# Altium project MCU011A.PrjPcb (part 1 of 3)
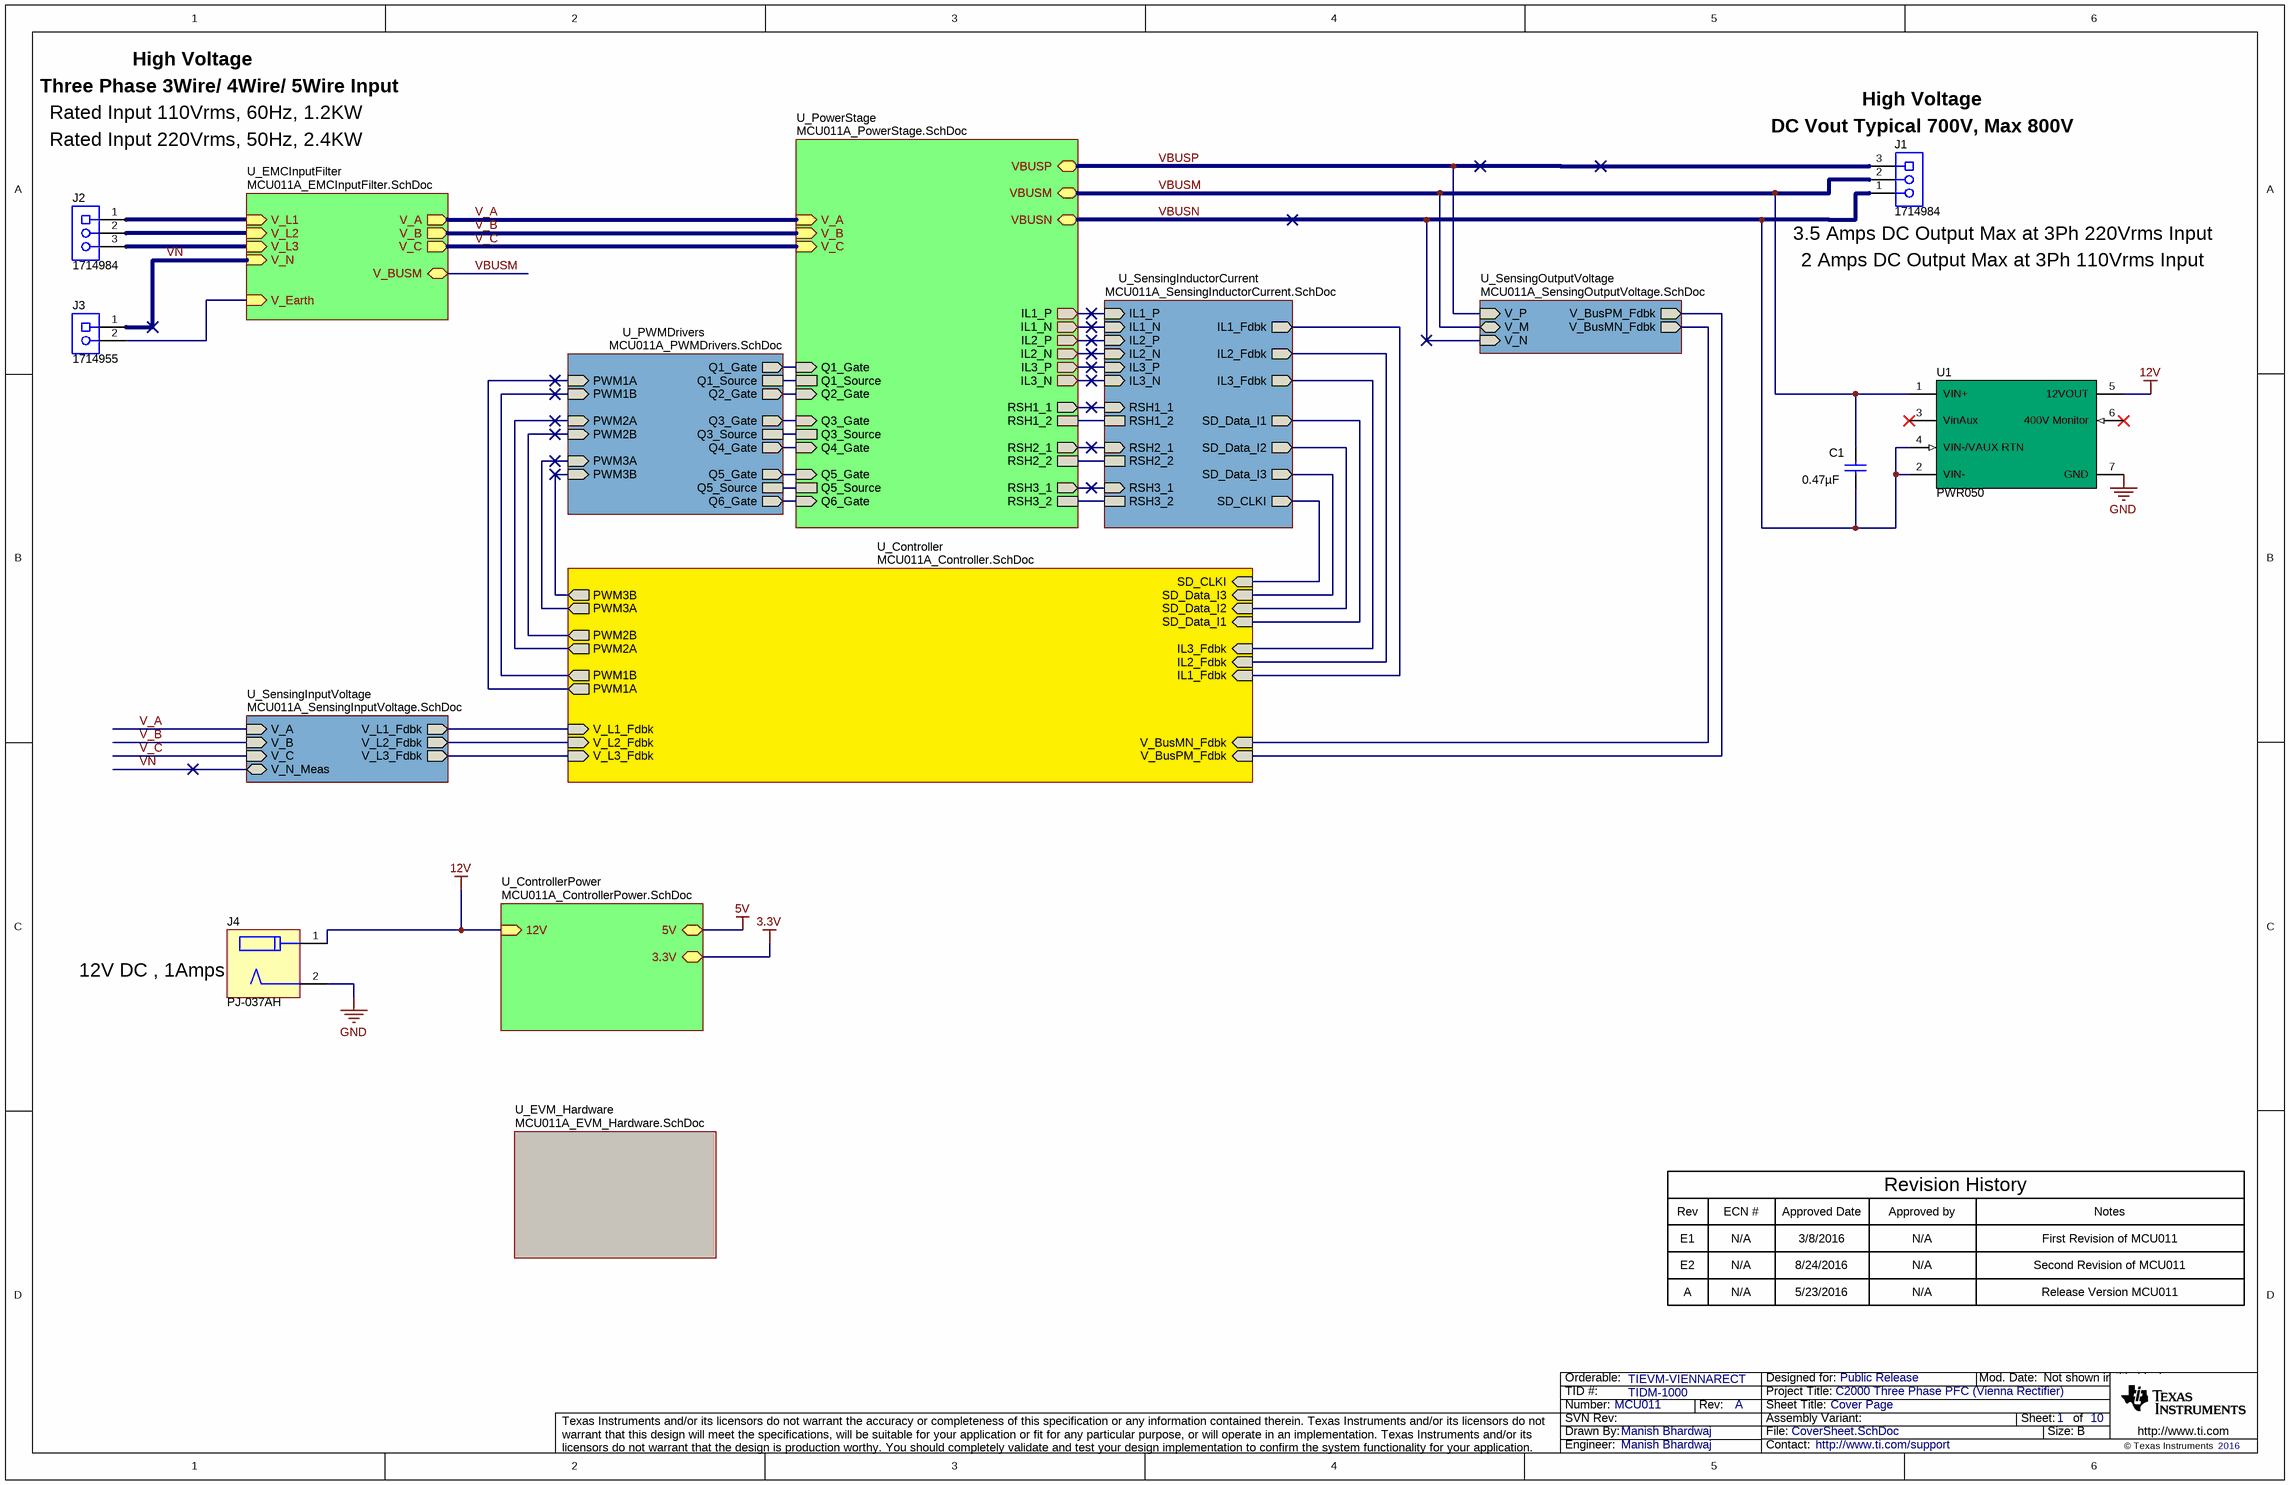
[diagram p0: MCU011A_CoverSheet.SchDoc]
CopyrightYear: 2016; EVM_orderable: TIEVM-VIENNARECT; PCB_Layout: TBD; PCB_Rev: A; PRJ_Customer: Public Release; PRJ_Engineer: Manish Bhardwaj; PRJ_Number: MCU011; PRJ_Title: C2000 Three Phase PFC (Vienna Rectifier); SCH_Rev: A; TechSupport: http://www.ti.com/support; TID: TIDM-1000
10 sheets, 500 parts. Net scope: hierarchical (ports join the sheet entries above them; power ports are global).
Board file: MCU011A_EVMBoard.PcbDoc
Sheets:
  MCU011A_CoverSheet.SchDoc
    U_PowerStage = MCU011A_PowerStage.SchDoc
    U_PWMDrivers = MCU011A_PWMDrivers.SchDoc
    U_ControllerPower = MCU011A_ControllerPower.SchDoc
    U_EVM_Hardware = MCU011A_EVM_Hardware.SchDoc
    U_EMCInputFilter = MCU011A_EMCInputFilter.SchDoc
    U_SensingInductorCurrent = MCU011A_SensingInductorCurrent.SchDoc
    U_SensingInputVoltage = MCU011A_SensingInputVoltage.SchDoc
    U_SensingOutputVoltage = MCU011A_SensingOutputVoltage.SchDoc
    U_Controller = MCU011A_Controller.SchDoc

## Sheet MCU011A_CoverSheet.SchDoc: Cover Page
size 431 x 279 mm; Date: Not shown in title block; ApprovedBy: Not shown in title block; CheckedBy: Not shown in title block; Author: Not shown in title block; CompanyName: Not shown in title block; DrawnBy: Manish Bhardwaj; Engineer: Not shown in title block; Organization: Not shown in title block; Address1: Not shown in title block; Address2: Not shown in title block; Address3: Not shown in title block; Address4: Not shown in title block; DocumentNumber: 1; Revision: Use project parameter SCH_Rev; SheetNumber: 1; SheetTotal: 10; PageSetup: Record=PageOptions¦CenterHorizontal=True¦CenterVertical=True¦PrintScale=1.00¦XCorrection=1.00¦YCorrection=1.00¦PrintKind=0¦BorderSize=5000000¦LeftOffset=0¦BottomOffset=0¦Orientation=2¦PaperLength=1000¦PaperWidth=1000¦Scale=100¦PaperSource=15¦PrintQuality=-3¦MediaType=1¦DitherType=10¦PrintScaleMode=1¦PaperKind=Letter (8.5 x 11")¦PaperIndex=1

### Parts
C1  ValueDisplayed: 0.47µF  [1812_254]  (hidden comment: 1812Y5000474KXTWS2)
J1  1714984  [Phoenix_1714984]
J2  1714984  [Phoenix_1714984]
J3  1714955  [Phoenix_1714955]
J4  PJ-037AH  [CUI_PJ-037AH]
U1  PWR050  [PWR050]

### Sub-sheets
U_Controller = MCU011A_Controller.SchDoc: PWM3A (out), PWM1A (out), PWM3B (out), SD_Data_I1 (in), SD_CLKI (in), SD_Data_I2 (in), SD_Data_I3 (in), V_L1_Fdbk (in), V_L2_Fdbk (in), V_L3_Fdbk (in), PWM1B (out), PWM2A (out), PWM2B (out), IL1_Fdbk (in), IL2_Fdbk (in), IL3_Fdbk (in), V_BusMN_Fdbk (in), V_BusPM_Fdbk (in)
U_ControllerPower = MCU011A_ControllerPower.SchDoc: 12V (in), 5V, 3.3V
U_EMCInputFilter = MCU011A_EMCInputFilter.SchDoc: V_N (in), V_L2 (in), V_L3 (in), V_L1 (in), V_Earth (in), V_C (out), V_B (out), V_A (out), V_BUSM
U_EVM_Hardware = MCU011A_EVM_Hardware.SchDoc: no entries
U_PowerStage = MCU011A_PowerStage.SchDoc: Q1_Gate (in), Q2_Gate (in), Q1_Source, Q3_Gate (in), Q4_Gate (in), Q3_Source, Q5_Gate (in), Q6_Gate (in), Q5_Source, RSH1_1 (out), RSH1_2, RSH2_1 (out), RSH2_2, RSH3_1 (out), RSH3_2, IL1_P (out), IL3_P (out), IL2_P (out), IL1_N (out), IL3_N (out), IL2_N (out), V_A (in), V_B (in), V_C (in), VBUSP, VBUSM, VBUSN
U_PWMDrivers = MCU011A_PWMDrivers.SchDoc: PWM1A (in), PWM1B (in), Q1_Gate (out), Q1_Source, PWM2A (in), PWM2B (in), Q3_Gate (out), Q4_Gate (out), Q3_Source, PWM3A (in), PWM3B (in), Q5_Gate (out), Q6_Gate (out), Q5_Source, Q2_Gate (out)
U_SensingInductorCurrent = MCU011A_SensingInductorCurrent.SchDoc: IL1_N (in), IL1_P (in), IL1_Fdbk (out), IL2_N (in), IL2_P (in), IL2_Fdbk (out), IL3_N (in), IL3_P (in), IL3_Fdbk (out), RSH1_1 (in), RSH1_2, SD_Data_I1 (out), SD_CLKI (out), RSH2_1 (in), RSH2_2, SD_Data_I2 (out), RSH3_1 (in), RSH3_2, SD_Data_I3 (out)
U_SensingInputVoltage = MCU011A_SensingInputVoltage.SchDoc: V_L1_Fdbk (out), V_A (in), V_L2_Fdbk (out), V_B (in), V_L3_Fdbk (out), V_C (in), V_N_Meas
U_SensingOutputVoltage = MCU011A_SensingOutputVoltage.SchDoc: V_BusPM_Fdbk (out), V_P (in), V_BusMN_Fdbk (out), V_N (in), V_M

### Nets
12V: J4.1 U1.5(12VOUT) ; sheet U_ControllerPower/12V
GND: J4.2 U1.7(GND)
IL1_Fdbk: sheet U_SensingInductorCurrent/IL1_Fdbk, sheet U_Controller/IL1_Fdbk
IL1_N: sheet U_PowerStage/IL1_N, sheet U_SensingInductorCurrent/IL1_N
IL1_P: sheet U_PowerStage/IL1_P, sheet U_SensingInductorCurrent/IL1_P
IL2_Fdbk: sheet U_SensingInductorCurrent/IL2_Fdbk, sheet U_Controller/IL2_Fdbk
IL2_N: sheet U_PowerStage/IL2_N, sheet U_SensingInductorCurrent/IL2_N
IL2_P: sheet U_PowerStage/IL2_P, sheet U_SensingInductorCurrent/IL2_P
IL3_Fdbk: sheet U_SensingInductorCurrent/IL3_Fdbk, sheet U_Controller/IL3_Fdbk
IL3_N: sheet U_PowerStage/IL3_N, sheet U_SensingInductorCurrent/IL3_N
IL3_P: sheet U_PowerStage/IL3_P, sheet U_SensingInductorCurrent/IL3_P
PWM1A: sheet U_PWMDrivers/PWM1A, sheet U_Controller/PWM1A
PWM1B: sheet U_PWMDrivers/PWM1B, sheet U_Controller/PWM1B
PWM2A: sheet U_PWMDrivers/PWM2A, sheet U_Controller/PWM2A
PWM2B: sheet U_PWMDrivers/PWM2B, sheet U_Controller/PWM2B
PWM3A: sheet U_PWMDrivers/PWM3A, sheet U_Controller/PWM3A
PWM3B: sheet U_PWMDrivers/PWM3B, sheet U_Controller/PWM3B
Q1_Gate: sheet U_PowerStage/Q1_Gate, sheet U_PWMDrivers/Q1_Gate
Q1_Source: sheet U_PowerStage/Q1_Source, sheet U_PWMDrivers/Q1_Source
Q2_Gate: sheet U_PowerStage/Q2_Gate, sheet U_PWMDrivers/Q2_Gate
Q3_Gate: sheet U_PowerStage/Q3_Gate, sheet U_PWMDrivers/Q3_Gate
Q3_Source: sheet U_PowerStage/Q3_Source, sheet U_PWMDrivers/Q3_Source
Q4_Gate: sheet U_PowerStage/Q4_Gate, sheet U_PWMDrivers/Q4_Gate
Q5_Gate: sheet U_PowerStage/Q5_Gate, sheet U_PWMDrivers/Q5_Gate
Q5_Source: sheet U_PowerStage/Q5_Source, sheet U_PWMDrivers/Q5_Source
Q6_Gate: sheet U_PowerStage/Q6_Gate, sheet U_PWMDrivers/Q6_Gate
RSH1_1: sheet U_PowerStage/RSH1_1, sheet U_SensingInductorCurrent/RSH1_1
RSH1_2: sheet U_PowerStage/RSH1_2, sheet U_SensingInductorCurrent/RSH1_2
RSH2_1: sheet U_PowerStage/RSH2_1, sheet U_SensingInductorCurrent/RSH2_1
RSH2_2: sheet U_PowerStage/RSH2_2, sheet U_SensingInductorCurrent/RSH2_2
RSH3_1: sheet U_PowerStage/RSH3_1, sheet U_SensingInductorCurrent/RSH3_1
RSH3_2: sheet U_PowerStage/RSH3_2, sheet U_SensingInductorCurrent/RSH3_2
SD_CLKI: sheet U_SensingInductorCurrent/SD_CLKI, sheet U_Controller/SD_CLKI
SD_Data_I1: sheet U_SensingInductorCurrent/SD_Data_I1, sheet U_Controller/SD_Data_I1
SD_Data_I2: sheet U_SensingInductorCurrent/SD_Data_I2, sheet U_Controller/SD_Data_I2
SD_Data_I3: sheet U_SensingInductorCurrent/SD_Data_I3, sheet U_Controller/SD_Data_I3
V_A: sheet U_PowerStage/V_A, sheet U_EMCInputFilter/V_A, sheet U_SensingInputVoltage/V_A
V_B: sheet U_PowerStage/V_B, sheet U_EMCInputFilter/V_B, sheet U_SensingInputVoltage/V_B
V_BusMN_Fdbk: sheet U_SensingOutputVoltage/V_BusMN_Fdbk, sheet U_Controller/V_BusMN_Fdbk
V_BusPM_Fdbk: sheet U_SensingOutputVoltage/V_BusPM_Fdbk, sheet U_Controller/V_BusPM_Fdbk
V_C: sheet U_PowerStage/V_C, sheet U_EMCInputFilter/V_C, sheet U_SensingInputVoltage/V_C
V_Earth: J3.2 ; sheet U_EMCInputFilter/V_Earth
V_L1: J2.1 ; sheet U_EMCInputFilter/V_L1
V_L1_Fdbk: sheet U_SensingInputVoltage/V_L1_Fdbk, sheet U_Controller/V_L1_Fdbk
V_L2: J2.2 ; sheet U_EMCInputFilter/V_L2
V_L2_Fdbk: sheet U_SensingInputVoltage/V_L2_Fdbk, sheet U_Controller/V_L2_Fdbk
V_L3: J2.3 ; sheet U_EMCInputFilter/V_L3
V_L3_Fdbk: sheet U_SensingInputVoltage/V_L3_Fdbk, sheet U_Controller/V_L3_Fdbk
VBUSM: C1.1 J1.2 U1.1(VIN+) ; sheet U_PowerStage/VBUSM, sheet U_EMCInputFilter/V_BUSM, sheet U_SensingOutputVoltage/V_M  [project net V_M]
VBUSN: C1.2 J1.1 U1.2(VIN-) U1.4(VIN-/VAUX_RTN) ; sheet U_PowerStage/VBUSN, sheet U_SensingOutputVoltage/V_N
VBUSP: J1.3 ; sheet U_PowerStage/VBUSP, sheet U_SensingOutputVoltage/V_P
VN: J3.1 ; sheet U_EMCInputFilter/V_N, sheet U_SensingInputVoltage/V_N_Meas  [project net V_N_Meas]

Not connected (* = marked no-connect by the designer): U1 3(VinAux)* 6(400V_Monitor)*

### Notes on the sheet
- High Voltage
- Three Phase 3Wire/ 4Wire/ 5Wire Input
- Rated Input 110Vrms, 60Hz, 1.2KW
- Rated Input 220Vrms, 50Hz, 2.4KW
- (near J1) DC Vout Typical 700V, Max 800V
- (near J1) 3.5 Amps DC Output Max at 3Ph 220Vrms Input
- 2 Amps DC Output Max at 3Ph 110Vrms Input
- 12V DC , 1Amps
- Rev
- E1
- ECN #
- N/A
- Approved Date
- 3/8/2016
- Approved by
- Revision History
- Notes
- First Revision of MCU011
- E2
- A
- 8/24/2016
- 5/23/2016
- Second Revision of MCU011
- Release Version MCU011

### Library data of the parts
C1 = 1812Y5000474KXTWS2: CAP, CERM, 0.47 µF, 500 V, +/- 10%, X7R, 1812; Manufacturer: Knowles Capacitors; Polarized: N; CompType: Capacitor; Value: 0.47uF; U/M: EA; Cap_F: 0.00000047; Tolerance_%: 10; Value1: Unknown; VDC_V: 500; Value2: 500V; TaMin_C: -55; TaMax_C: 125; Cap_Case: 1812; SizeArea_mm2: 14.4; SizeAreaWB_mm2: 23.1; SizeX_mm: 4.5; SizeY_mm: 3.2; SizeZ_mm: 2.54; AEC Category: Q200
J1 J2 = 1714984: Terminal Block, 3x1, 9.52MM, TH; Manufacturer: Phoenix Contact; SymbolCreator: a0412235
J3 = 1714955: Terminal Block, 2x1, 6.35mm, Green, TH; Manufacturer: Phoenix Contact; SymbolCreator: a0412235; Pitch_mm: 6.35; Gender: Female; Shrouded: Y; Row_Count: 1
J4 = PJ-037AH: Power Jack, 2mm, R/A, TH; Manufacturer: CUI Inc.; SymbolCreator: Altium; Pitch_mm: 6; Gender: Male; Shrouded: N; Row_Count: 1
U1 = PWR050: PCBA, UCC28600EVM-400V-12V; Manufacturer: Texas Instruments; SymbolCreator: a0412235

## Sheet MCU011A_PowerStage.SchDoc: Vienna Rectifier Power Stage
size 558 x 431 mm; Date: Not shown in title block; ApprovedBy: Not shown in title block; CheckedBy: Not shown in title block; Author: Not shown in title block; CompanyName: Not shown in title block; DrawnBy: Manish Bhardwaj; Engineer: Not shown in title block; Organization: Not shown in title block; Address1: Not shown in title block; Address2: Not shown in title block; Address3: Not shown in title block; Address4: Not shown in title block; DocumentNumber: 1; Revision: Use project parameter SCH_Rev; SheetNumber: 3; SheetTotal: 10; PageSetup: Record=PageOptions¦CenterHorizontal=True¦CenterVertical=True¦PrintScale=1.00¦XCorrection=1.00¦YCorrection=1.00¦PrintKind=0¦BorderSize=5000000¦LeftOffset=0¦BottomOffset=0¦Orientation=2¦PaperLength=1000¦PaperWidth=1000¦Scale=100¦PaperSource=15¦PrintQuality=600¦MediaType=1¦DitherType=10¦PaperKind=Letter¦PrintScaleMode=1
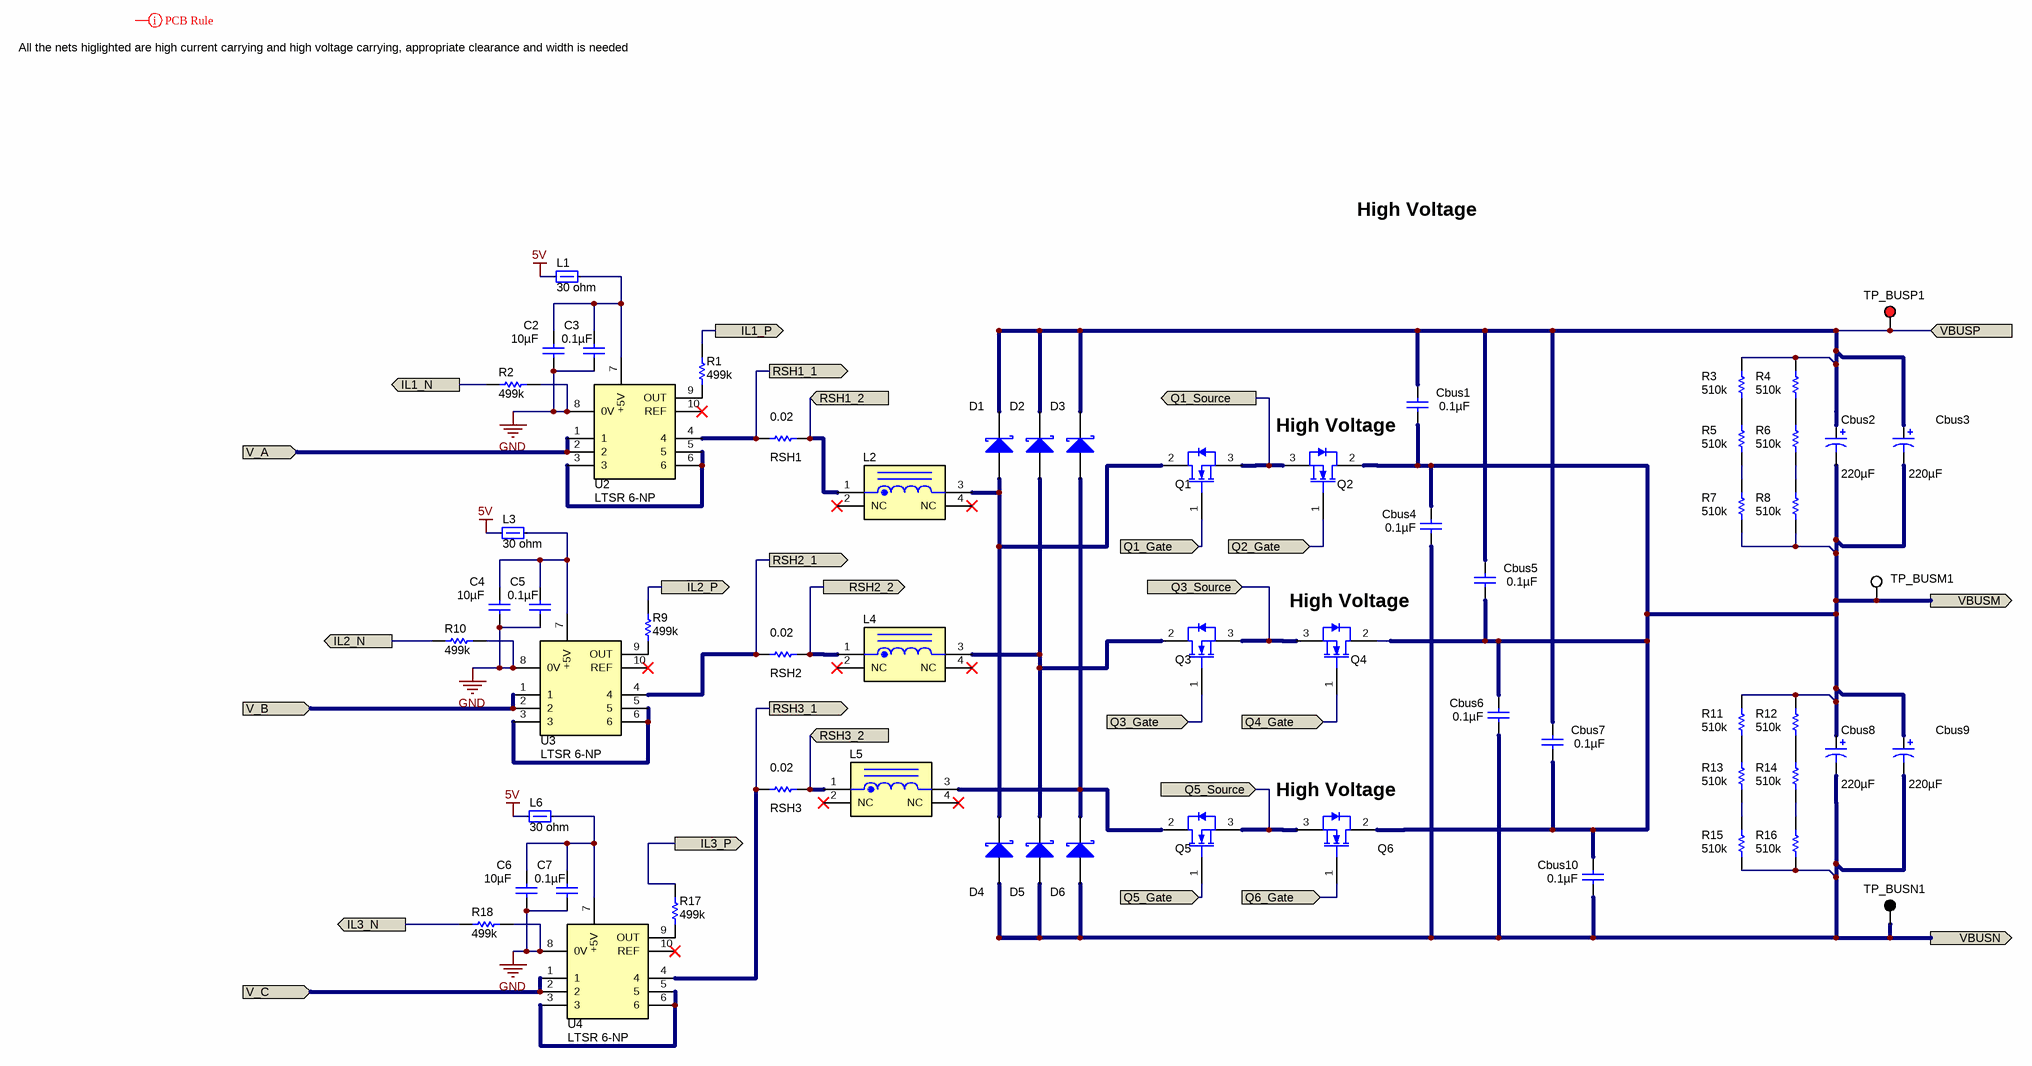
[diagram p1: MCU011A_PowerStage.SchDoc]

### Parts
C2  ValueDisplayed: 10µF  [1206_190]  (hidden comment: C1206C106K3RACTU)
C3  ValueDisplayed: 0.1µF  [0805_HV]  (hidden comment: C0805C104K3RACTU)
C4  ValueDisplayed: 10µF  [1206_190]  (hidden comment: C1206C106K3RACTU)
C5  ValueDisplayed: 0.1µF  [0805_HV]  (hidden comment: C0805C104K3RACTU)
C6  ValueDisplayed: 10µF  [1206_190]  (hidden comment: C1206C106K3RACTU)
C7  ValueDisplayed: 0.1µF  [0805_HV]  (hidden comment: C0805C104K3RACTU)
Cbus1  ValueDisplayed: 0.1µF  [CAPRR1500W80L1800T770H1210]  (hidden comment: ECW-F6104JL)
Cbus2  ValueDisplayed: 220µF  [B43504_3500x3000]  (hidden comment: B43504C5227M)
Cbus3  ValueDisplayed: 220µF  [B43504_3500x3000]  (hidden comment: B43504C5227M)
Cbus4  ValueDisplayed: 0.1µF  [CAPRR1500W80L1800T770H1210]  (hidden comment: ECW-F6104JL)
Cbus5  ValueDisplayed: 0.1µF  [CAPRR1500W80L1800T770H1210]  (hidden comment: ECW-F6104JL)
Cbus6  ValueDisplayed: 0.1µF  [CAPRR1500W80L1800T770H1210]  (hidden comment: ECW-F6104JL)
Cbus7  ValueDisplayed: 0.1µF  [CAPRR1500W80L1800T770H1210]  (hidden comment: ECW-F6104JL)
Cbus8  ValueDisplayed: 220µF  [B43504_3500x3000]  (hidden comment: B43504C5227M)
Cbus9  ValueDisplayed: 220µF  [B43504_3500x3000]  (hidden comment: B43504C5227M)
Cbus10  ValueDisplayed: 0.1µF  [CAPRR1500W80L1800T770H1210]  (hidden comment: ECW-F6104JL)
D1  C4D08120A  [TO-220-2_HORIZ_INV]  (value not drawn)
D2  C4D08120A  [TO-220-2_HORIZ_INV]  (value not drawn)
D3  C4D08120A  [TO-220-2_HORIZ_INV]  (value not drawn)
D4  C4D08120A  [TO-220-2_HORIZ_INV]  (value not drawn)
D5  C4D08120A  [TO-220-2_HORIZ_INV]  (value not drawn)
D6  C4D08120A  [TO-220-2_HORIZ_INV]  (value not drawn)
L1  value 30 ohm  [0805_HV]  (hidden comment: MPZ2012S300AT000)
L2  53PR116-292  [53PR116]  (value not drawn)
L3  value 30 ohm  [0805_HV]  (hidden comment: MPZ2012S300AT000)
L4  53PR116-292  [53PR116]  (value not drawn)
L5  53PR116-292  [53PR116]  (value not drawn)
L6  value 30 ohm  [0805_HV]  (hidden comment: MPZ2012S300AT000)
Q1  IPP65R190C7FKSA1  [TO-220AB_HORIZONTAL]  (value not drawn)
Q2  IPP65R190C7FKSA1  [TO-220AB_HORIZONTAL]  (value not drawn)
Q3  IPP65R190C7FKSA1  [TO-220AB_HORIZONTAL]  (value not drawn)
Q4  IPP65R190C7FKSA1  [TO-220AB_HORIZONTAL]  (value not drawn)
Q5  IPP65R190C7FKSA1  [TO-220AB_HORIZONTAL]  (value not drawn)
Q6  IPP65R190C7FKSA1  [TO-220AB_HORIZONTAL]  (value not drawn)
R1  ValueDisplayed: 499k  [0603]  (hidden comment: ERJ-3EKF4993V)
R2  ValueDisplayed: 499k  [0603]  (hidden comment: ERJ-3EKF4993V)
R3  ValueDisplayed: 510k  [2010]  (hidden comment: CRCW2010510KJNEF)
R4  ValueDisplayed: 510k  [2010]  (hidden comment: CRCW2010510KJNEF)
R5  ValueDisplayed: 510k  [2010]  (hidden comment: CRCW2010510KJNEF)
R6  ValueDisplayed: 510k  [2010]  (hidden comment: CRCW2010510KJNEF)
R7  ValueDisplayed: 510k  [2010]  (hidden comment: CRCW2010510KJNEF)
R8  ValueDisplayed: 510k  [2010]  (hidden comment: CRCW2010510KJNEF)
R9  ValueDisplayed: 499k  [0603]  (hidden comment: ERJ-3EKF4993V)
R10  ValueDisplayed: 499k  [0805]  (hidden comment: CRCW0805499KFKEA)
R11  ValueDisplayed: 510k  [2010]  (hidden comment: CRCW2010510KJNEF)
R12  ValueDisplayed: 510k  [2010]  (hidden comment: CRCW2010510KJNEF)
R13  ValueDisplayed: 510k  [2010]  (hidden comment: CRCW2010510KJNEF)
R14  ValueDisplayed: 510k  [2010]  (hidden comment: CRCW2010510KJNEF)
R15  ValueDisplayed: 510k  [2010]  (hidden comment: CRCW2010510KJNEF)
R16  ValueDisplayed: 510k  [2010]  (hidden comment: CRCW2010510KJNEF)
R17  ValueDisplayed: 499k  [0603]  (hidden comment: ERJ-3EKF4993V)
R18  ValueDisplayed: 499k  [0603]  (hidden comment: ERJ-3EKF4993V)
RSH1  ValueDisplayed: 0.02  [2512]  (hidden comment: CRA2512-FZ-R020ELF)
RSH2  ValueDisplayed: 0.02  [2512]  (hidden comment: CRA2512-FZ-R020ELF)
RSH3  ValueDisplayed: 0.02  [2512]  (hidden comment: CRA2512-FZ-R020ELF)
TP_BUSM1  5012  [Keystone5012]  (value not drawn)
TP_BUSN1  5011  [Keystone5011]  (value not drawn)
TP_BUSP1  5010  [Keystone5010]  (value not drawn)
U2  LTSR 6-NP  [LTSR6-NP]
U3  LTSR 6-NP  [LTSR6-NP]
U4  LTSR 6-NP  [LTSR6-NP]

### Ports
IL1_N (out), IL1_P (out), IL2_N (out), IL2_P (out), IL3_N (out), IL3_P (out), Q1_Gate (in), Q1_Source, Q2_Gate (in), Q3_Gate (in), Q3_Source, Q4_Gate (in), Q5_Gate (in), Q5_Source, Q6_Gate (in), RSH1_1 (out), RSH1_2, RSH2_1 (out), RSH2_2, RSH3_1 (out), RSH3_2, V_A (in), V_B (in), V_C (in), VBUSM, VBUSN, VBUSP

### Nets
5V: L1.2 L3.2 L6.2
GND: C2.2 C3.2 C4.2 C5.2 C6.2 C7.2 R2.2 R10.2 R18.2 U2.8(0V) U3.8(0V) U4.8(0V)
IL1_N: R2.1 ; port IL1_N
IL1_P: R1.2 ; port IL1_P
IL2_N: R10.1 ; port IL2_N
IL2_P: R9.2 ; port IL2_P
IL3_N: R18.1 ; port IL3_N
IL3_P: R17.2 ; port IL3_P
Q1_Gate: Q1.1(G) ; port Q1_Gate
Q1_Source: Q1.3(S) Q2.3(S) ; port Q1_Source
Q2_Gate: Q2.1(G) ; port Q2_Gate
Q3_Gate: Q3.1(G) ; port Q3_Gate
Q3_Source: Q3.3(S) Q4.3(S) ; port Q3_Source
Q4_Gate: Q4.1(G) ; port Q4_Gate
Q5_Gate: Q5.1(G) ; port Q5_Gate
Q5_Source: Q5.3(S) Q6.3(S) ; port Q5_Source
Q6_Gate: Q6.1(G) ; port Q6_Gate
RSH1_1: RSH1.1 U2.4 ; port RSH1_1
RSH1_2: L2.1 RSH1.2 ; port RSH1_2
RSH2_1: RSH2.1 U3.4 ; port RSH2_1
RSH2_2: L4.1 RSH2.2 ; port RSH2_2
RSH3_1: RSH3.1 U4.4 ; port RSH3_1
RSH3_2: L5.1 RSH3.2 ; port RSH3_2
V_A: U2.1 U2.2 ; port V_A
V_B: U3.1 U3.2 ; port V_B
V_C: U4.1 U4.2 ; port V_C
V_M: Cbus1.2 Cbus2.2(-) Cbus3.2(-) Cbus4.1 Cbus5.2 Cbus6.1 Cbus7.2 Cbus8.1(+) Cbus9.1(+) Cbus10.1 Q2.2(D) Q4.2(D) Q6.2(D) R7.1 R8.1 R11.2 R12.2 TP_BUSM1.1 ; port VBUSM
VBUSN: Cbus4.2 Cbus6.2 Cbus8.2(-) Cbus9.2(-) Cbus10.2 D4.2(A) D5.2(A) D6.2(A) R15.1 R16.1 TP_BUSN1.1 ; port VBUSN
VBUSP: Cbus1.1 Cbus2.1(+) Cbus3.1(+) Cbus5.1 Cbus7.1 D1.1(K) D2.1(K) D3.1(K) R3.2 R4.2 TP_BUSP1.1 ; port VBUSP
NetC2_1: C2.1 C3.1 L1.1 U2.7(+5V)
NetC4_1: C4.1 C5.1 L3.1 U3.7(+5V)
NetC6_1: C6.1 C7.1 L6.1 U4.7(+5V)
NetD1_2: D1.2(A) D4.1(K) L2.3 Q1.2(D)
NetD2_2: D2.2(A) D5.1(K) L4.3 Q3.2(D)
NetD3_2: D3.2(A) D6.1(K) L5.3 Q5.2(D)
NetR1_1: R1.1 U2.9(OUT)
NetR3_1: R3.1 R5.2
NetR4_1: R4.1 R6.2
NetR5_1: R5.1 R7.2
NetR6_1: R6.1 R8.2
NetR9_1: R9.1 U3.9(OUT)
NetR11_1: R11.1 R13.2
NetR12_1: R12.1 R14.2
NetR13_1: R13.1 R15.2
NetR14_1: R14.1 R16.2
NetR17_1: R17.1 U4.9(OUT)
NetU2_3: U2.3 U2.5 U2.6
NetU3_3: U3.3 U3.5 U3.6
NetU4_3: U4.3 U4.5 U4.6

Not connected (* = marked no-connect by the designer): L2 2(NC)* 4(NC)*; L4 2(NC)* 4(NC)*; L5 2(NC)* 4(NC)*; U2 10(REF)*; U3 10(REF)*; U4 10(REF)*

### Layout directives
rule Undefined: (no net found under the mark)

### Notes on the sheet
- All the nets higlighted are high current carrying and high voltage carrying, appropriate clearance and width is needed
- High Voltage
- (near Q4) High Voltage
- (near Q6) High Voltage

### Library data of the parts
C2 C4 C6 = C1206C106K3RACTU: CAP, CERM, 10 µF, 25 V, +/- 10%, X7R, 1206_190; Manufacturer: Kemet; Polarized: N; CompType: Capacitor; Value: 10uF; U/M: EA; Cap_F: 0.00001; Tolerance_%: 10; Value1: Unknown; VDC_V: 25; Value2: 25V; TaMin_C: -55; TaMax_C: 125; Cap_Case: 1206; AEC Category: Q200
C3 C5 C7 = C0805C104K3RACTU: CAP, CERM, 0.1 µF, 25 V, +/- 10%, X7R, 0805; Manufacturer: Kemet; Polarized: N; CompType: Capacitor; Value: 0.1uF; U/M: EA; Cap_F: 0.0000001; Tolerance_%: 10; ESR_ohm: 0.064; Value1: 0.064 ohm; VDC_V: 25; Value2: 25V; IRMS_A: 1.64; TaMin_C: -55; TaMax_C: 125; Cap_Case: 0805; AEC Category: Q200
Cbus1 Cbus4-Cbus7 Cbus10 = ECW-F6104JL: CAP, Film, 0.1 µF, 630 V, +/- 5%, TH; Manufacturer: Panasonic; Polarized: N; CompType: Capacitor; Value: 0.1uF; U/M: EA; Cap_F: 0.0000001; Tolerance_%: 5; Value1: Unknown; VDC_V: 630; Value2: 630V; TaMin_C: -40; TaMax_C: 105; Cap_Case: Radial 18x7.7x13.6; AEC Category: Q200
Cbus2 Cbus3 Cbus8 Cbus9 = B43504C5227M: CAP, AL, 220 µF, 450 V, +/- 20%, 0.73 ohm, TH; Manufacturer: TDK; Polarized: Y; CompType: Capacitor; Value: 220uF; U/M: EA; Cap_F: 0.00022; Tolerance_%: 20; VDC_V: 450; Value2: 450V; ESR_ohm: 0.73; IRMS_A: 1.2; TaMin_C: -40; TaMax_C: 105; Cap_Case: 35x30mm; AEC Category: Q200; AEC Qualified: N
D1-D6 = C4D08120A: Diode, Schottky, 1200 V, 8 A, TH; Manufacturer: Cree; U/M: EA; Vf_V: 1.8; Value: 1200V; Value1: 8A; Value2: 1.8V; Io_A: 8; Vr_V: 1200; TJmax_C: 175; RJC_CperW: 1.26; AEC Category: Q101; AEC Qualified: N
L1 L3 L6 = MPZ2012S300AT000: Ferrite Bead, 30 ohm @ 100 MHz, 6 A, 0805; Manufacturer: TDK; Imax_A: 6; DCR_ohm: 0.01; Value1: 0.01 ohm; Value2: 6A; ZTyp@100MHz_Ohm: 30
L2 L4 L5 = 53PR116-292: Inductor, 0.2 ohm, TH; Manufacturer: Vitec Corporation; SymbolCreator: a0411947; DCR_ohm: 0.2; Value1: 0.2 ohm; Value2: A; SizeAreaWB_mm2: 2452.56; SizeArea_mm2: 2258.06; SizeX_mm: 44.45; SizeY_mm: 50.8; SizeZ_mm: 53.34; AEC Category: Q200; AEC Qualified: N
Q1-Q6 = IPP65R190C7: MOSFET, N-CH, 700 V, 13 A, TO-220AB; Manufacturer: Infineon Technologies; Alternate Manufacturer: None; U/M: EA; ChType: N; Value: 700V; VdsMax_V: 700; Value1: ? ohm; Value2: 23 nC; QgTyp_nC: 23; Vgs_V: 20; IdsMax_A: 13; AEC Category: Q101
R1 R2 R9 R17 R18 = ERJ-3EKF4993V: RES, 499 k, 1%, 0.1 W, AEC-Q200 Grade 0, 0603; Manufacturer: Panasonic; CompType: Resistor; Value: 499k; Res_ohm: 499000; Tolerance_%: 1; Power_W: 0.1; Value2: 0.1W; VDC_V: 75; TempCo: 100 ppm/C; SizeArea_mm2: 1.28; SizeX_mm: 1.6; SizeY_mm: 0.8; EIA_Code: E96; U/M: EA; AEC Category: Q200; AEC Qualified: Y; AEC Grade: 0
R3-R8 R11-R16 = CRCW2010510KJNEF: RES, 510 k, 5%, 0.75 W, AEC-Q200 Grade 0, 2010; Manufacturer: Vishay-Dale; CompType: Resistor; Value: 510k; Res_ohm: 510000; Tolerance_%: 5; Power_W: 0.75; Value2: 0.75W; VDC_V: 400; TempCo: 200 ppm/C; SizeArea_mm2: 12.5; SizeY_mm: 2.5; SizeZ_mm: 1.66; EIA_Code: E24; U/M: EA; AEC Category: Q200; AEC Qualified: Y; AEC Grade: 0
R10 = CRCW0805499KFKEA: RES, 499 k, 1%, 0.125 W, 0805; Manufacturer: Vishay-Dale; CompType: Resistor; Value: 499k; Res_ohm: 499000; Tolerance_%: 1; Power_W: 0.125; Value2: 0.125W; VDC_V: 150; TempCo: 100 ppm/C; EIA_Code: E96; U/M: EA; AEC Category: Q200
RSH1-RSH3 = CRA2512-FZ-R020ELF: RES, 0.02, 1%, 3 W, 2512; Manufacturer: Bourns; CompType: Resistor; Value: 0.02; Value_Code: R020; Tolerance_%: 1; Power_W: 3; Value2: 3W; TempCo: 75 ppm/C; EIA_Code: E96; U/M: EA; AEC Category: Q200
TP_BUSM1 = 5012: Test Point, Multipurpose, White, TH; Manufacturer: Keystone; CompType: Test Point Loop; ContactFinish: Silver
TP_BUSN1 = 5011: Test Point, Multipurpose, Black, TH; Manufacturer: Keystone; CompType: Test Point Loop; ContactFinish: Silver
TP_BUSP1 = 5010: Test Point, Multipurpose, Red, TH; Manufacturer: Keystone; CompType: Test Point Loop; ContactFinish: Silver
U2-U4 = LTSR 6-NP: Current Transducer, AC/DC, 6A, TH; Manufacturer: LEM; SymbolCreator: Altium

## Sheet MCU011A_PWMDrivers.SchDoc: PWM Gate Drivers
size 431 x 279 mm; Date: Not shown in title block; ApprovedBy: Not shown in title block; CheckedBy: Not shown in title block; Author: Not shown in title block; CompanyName: Not shown in title block; DrawnBy: Manish Bhardwaj; Engineer: Not shown in title block; Organization: Not shown in title block; Address1: Not shown in title block; Address2: Not shown in title block; Address3: Not shown in title block; Address4: Not shown in title block; DocumentNumber: 1; Revision: Use project parameter SCH_Rev; SheetNumber: 4; SheetTotal: 10; PageSetup: Record=PageOptions¦CenterHorizontal=True¦CenterVertical=True¦PrintScale=1.00¦XCorrection=1.00¦YCorrection=1.00¦PrintKind=0¦BorderSize=5000000¦LeftOffset=0¦BottomOffset=0¦Orientation=2¦PaperLength=1000¦PaperWidth=1000¦Scale=100¦PaperSource=15¦PrintQuality=600¦MediaType=1¦DitherType=10¦PaperKind=Letter¦PrintScaleMode=1
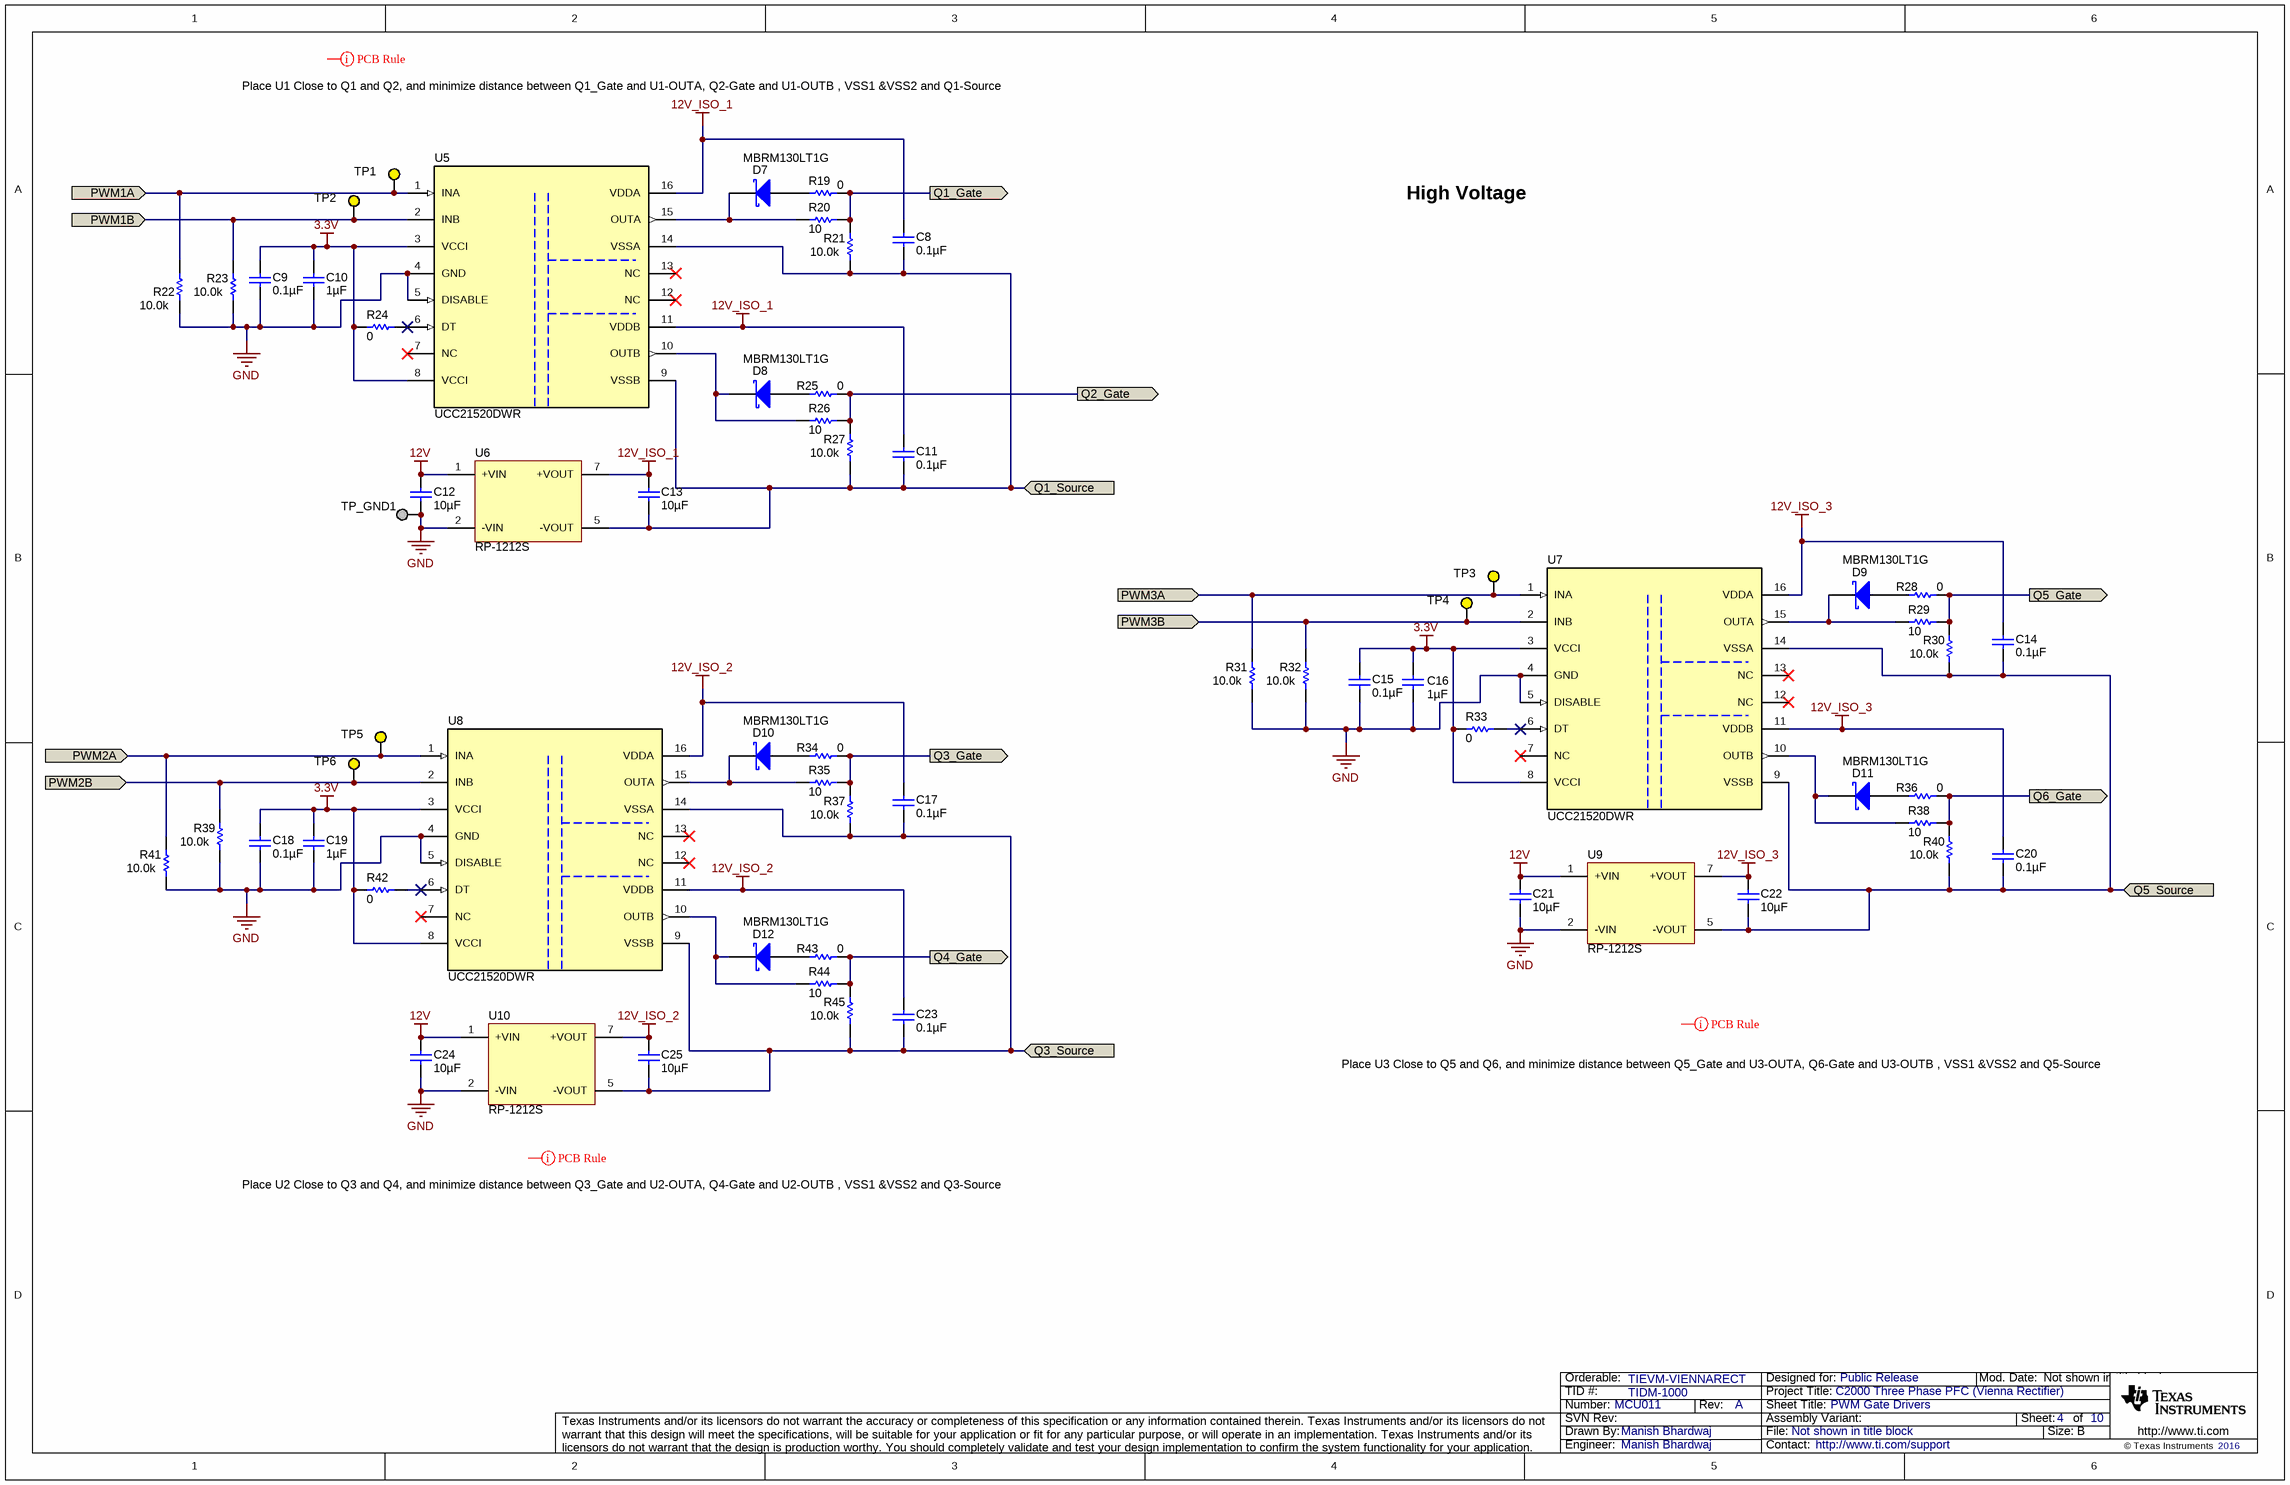
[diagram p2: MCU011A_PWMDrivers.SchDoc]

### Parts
C8  ValueDisplayed: 0.1µF  [0805_HV]  (hidden comment: C0805C104K3RACTU)
C9  ValueDisplayed: 0.1µF  [0805_HV]  (hidden comment: C0805C104K3RACTU)
C10  ValueDisplayed: 1µF  [0805_HV]  (hidden comment: GRM21BR71H105KA12L)
C11  ValueDisplayed: 0.1µF  [0805_HV]  (hidden comment: C0805C104K3RACTU)
C12  ValueDisplayed: 10µF  [1206_190]  (hidden comment: C1206C106K3RACTU)
C13  ValueDisplayed: 10µF  [1206_190]  (hidden comment: C1206C106K3RACTU)
C14  ValueDisplayed: 0.1µF  [0805_HV]  (hidden comment: C0805C104K3RACTU)
C15  ValueDisplayed: 0.1µF  [0805_HV]  (hidden comment: C0805C104K3RACTU)
C16  ValueDisplayed: 1µF  [0805_HV]  (hidden comment: GRM21BR71H105KA12L)
C17  ValueDisplayed: 0.1µF  [0805_HV]  (hidden comment: C0805C104K3RACTU)
C18  ValueDisplayed: 0.1µF  [0805_HV]  (hidden comment: C0805C104K3RACTU)
C19  ValueDisplayed: 1µF  [0805_HV]  (hidden comment: GRM21BR71H105KA12L)
C20  ValueDisplayed: 0.1µF  [0805_HV]  (hidden comment: C0805C104K3RACTU)
C21  ValueDisplayed: 10µF  [1206_190]  (hidden comment: C1206C106K3RACTU)
C22  ValueDisplayed: 10µF  [1206_190]  (hidden comment: C1206C106K3RACTU)
C23  ValueDisplayed: 0.1µF  [0805_HV]  (hidden comment: C0805C104K3RACTU)
C24  ValueDisplayed: 10µF  [1206_190]  (hidden comment: C1206C106K3RACTU)
C25  ValueDisplayed: 10µF  [1206_190]  (hidden comment: C1206C106K3RACTU)
D7  MBRM130LT1G  [POWERMITE]
D8  MBRM130LT1G  [POWERMITE]
D9  MBRM130LT1G  [POWERMITE]
D10  MBRM130LT1G  [POWERMITE]
D11  MBRM130LT1G  [POWERMITE]
D12  MBRM130LT1G  [POWERMITE]
R19  ValueDisplayed: 0  [0805_HV]  (hidden comment: CRCW08050000Z0EA)
R20  ValueDisplayed: 10  [0805_HV]  (hidden comment: CRCW080510R0JNEA)
R21  ValueDisplayed: 10.0k  [0805_HV]  (hidden comment: RT0805BRD0710KL)
R22  ValueDisplayed: 10.0k  [0805]  (hidden comment: RT0805BRD0710KL)
R23  ValueDisplayed: 10.0k  [0805]  (hidden comment: RT0805BRD0710KL)
R24  ValueDisplayed: 0  [0805]  (hidden comment: CRCW08050000Z0EA)
R25  ValueDisplayed: 0  [0805_HV]  (hidden comment: CRCW08050000Z0EA)
R26  ValueDisplayed: 10  [0805_HV]  (hidden comment: CRCW080510R0JNEA)
R27  ValueDisplayed: 10.0k  [0805_HV]  (hidden comment: RT0805BRD0710KL)
R28  ValueDisplayed: 0  [0805_HV]  (hidden comment: CRCW08050000Z0EA)
R29  ValueDisplayed: 10  [0805_HV]  (hidden comment: CRCW080510R0JNEA)
R30  ValueDisplayed: 10.0k  [0805_HV]  (hidden comment: RT0805BRD0710KL)
R31  ValueDisplayed: 10.0k  [0805]  (hidden comment: RT0805BRD0710KL)
R32  ValueDisplayed: 10.0k  [0805]  (hidden comment: RT0805BRD0710KL)
R33  ValueDisplayed: 0  [0805]  (hidden comment: CRCW08050000Z0EA)
R34  ValueDisplayed: 0  [0805_HV]  (hidden comment: CRCW08050000Z0EA)
R35  ValueDisplayed: 10  [0805_HV]  (hidden comment: CRCW080510R0JNEA)
R36  ValueDisplayed: 0  [0805_HV]  (hidden comment: CRCW08050000Z0EA)
R37  ValueDisplayed: 10.0k  [0805_HV]  (hidden comment: RT0805BRD0710KL)
R38  ValueDisplayed: 10  [0805_HV]  (hidden comment: CRCW080510R0JNEA)
R39  ValueDisplayed: 10.0k  [0805]  (hidden comment: RT0805BRD0710KL)
R40  ValueDisplayed: 10.0k  [0805_HV]  (hidden comment: RT0805BRD0710KL)
R41  ValueDisplayed: 10.0k  [0805]  (hidden comment: RT0805BRD0710KL)
R42  ValueDisplayed: 0  [0805]  (hidden comment: CRCW08050000Z0EA)
R43  ValueDisplayed: 0  [0805_HV]  (hidden comment: CRCW08050000Z0EA)
R44  ValueDisplayed: 10  [0805_HV]  (hidden comment: CRCW080510R0JNEA)
R45  ValueDisplayed: 10.0k  [0805_HV]  (hidden comment: RT0805BRD0710KL)
TP1  5014  [Keystone5014]  (value not drawn)
TP2  5014  [Keystone5014]  (value not drawn)
TP3  5014  [Keystone5014]  (value not drawn)
TP4  5014  [Keystone5014]  (value not drawn)
TP5  5014  [Keystone5014]  (value not drawn)
TP6  5014  [Keystone5014]  (value not drawn)
TP_GND1  5128  [Keystone5128]  (value not drawn)
U5  UCC21520DWR  [DW0016B_N]
U6  RP-1212S  [RP-1205S]
U7  UCC21520DWR  [DW0016B_N]
U8  UCC21520DWR  [DW0016B_N]
U9  RP-1212S  [RP-1205S]
U10  RP-1212S  [RP-1205S]

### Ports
PWM1A (in), PWM1B (in), PWM2A (in), PWM2B (in), PWM3A (in), PWM3B (in), Q1_Gate (out), Q1_Source, Q2_Gate (out), Q3_Gate (out), Q3_Source, Q4_Gate (out), Q5_Gate (out), Q5_Source, Q6_Gate (out)

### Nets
3.3V: C9.1 C10.1 C15.1 C16.1 C18.1 C19.1 R24.2 R33.2 R42.2 U5.3(VCCI) U5.8(VCCI) U7.3(VCCI) U7.8(VCCI) U8.3(VCCI) U8.8(VCCI)
12V: C12.1 C21.1 C24.1 U6.1(+VIN) U9.1(+VIN) U10.1(+VIN)
12V_ISO_1: C8.1 C11.1 C13.1 U5.11(VDDB) U5.16(VDDA) U6.7(+VOUT)
12V_ISO_2: C17.1 C23.1 C25.1 U8.11(VDDB) U8.16(VDDA) U10.7(+VOUT)
12V_ISO_3: C14.1 C20.1 C22.1 U7.11(VDDB) U7.16(VDDA) U9.7(+VOUT)
GND: C9.2 C10.2 C12.2 C15.2 C16.2 C18.2 C19.2 C21.2 C24.2 R22.1 R23.1 R31.1 R32.1 R39.1 R41.1 TP_GND1.1 U5.4(GND) U5.5(DISABLE) U6.2(-VIN) U7.4(GND) U7.5(DISABLE) U8.4(GND) U8.5(DISABLE) U9.2(-VIN) U10.2(-VIN)
PWM1A: R22.2 TP1.1 U5.1(INA) ; port PWM1A
PWM1B: R23.2 TP2.1 U5.2(INB) ; port PWM1B
PWM2A: R41.2 TP5.1 U8.1(INA) ; port PWM2A
PWM2B: R39.2 TP6.1 U8.2(INB) ; port PWM2B
PWM3A: R31.2 TP3.1 U7.1(INA) ; port PWM3A
PWM3B: R32.2 TP4.1 U7.2(INB) ; port PWM3B
Q1_Gate: R19.1 R20.2 R21.2 ; port Q1_Gate
Q1_Source: C8.2 C11.2 C13.2 R21.1 R27.1 U5.9(VSSB) U5.14(VSSA) U6.5(-VOUT) ; port Q1_Source
Q2_Gate: R25.1 R26.2 R27.2 ; port Q2_Gate
Q3_Gate: R34.1 R35.2 R37.2 ; port Q3_Gate
Q3_Source: C17.2 C23.2 C25.2 R37.1 R45.1 U8.9(VSSB) U8.14(VSSA) U10.5(-VOUT) ; port Q3_Source
Q4_Gate: R43.1 R44.2 R45.2 ; port Q4_Gate
Q5_Gate: R28.1 R29.2 R30.2 ; port Q5_Gate
Q5_Source: C14.2 C20.2 C22.2 R30.1 R40.1 U7.9(VSSB) U7.14(VSSA) U9.5(-VOUT) ; port Q5_Source
Q6_Gate: R36.1 R38.2 R40.2 ; port Q6_Gate
NetD7_1: D7.1(K) R20.1 U5.15(OUTA)
NetD7_2: D7.2(A) R19.2
NetD8_1: D8.1(K) R26.1 U5.10(OUTB)
NetD8_2: D8.2(A) R25.2
NetD9_1: D9.1(K) R29.1 U7.15(OUTA)
NetD9_2: D9.2(A) R28.2
NetD10_1: D10.1(K) R35.1 U8.15(OUTA)
NetD10_2: D10.2(A) R34.2
NetD11_1: D11.1(K) R38.1 U7.10(OUTB)
NetD11_2: D11.2(A) R36.2
NetD12_1: D12.1(K) R44.1 U8.10(OUTB)
NetD12_2: D12.2(A) R43.2
NetR24_1: R24.1 U5.6(DT)
NetR33_1: R33.1 U7.6(DT)
NetR42_1: R42.1 U8.6(DT)

Not connected (* = marked no-connect by the designer): U5 7(NC)* 12(NC)* 13(NC)*; U7 7(NC)* 12(NC)* 13(NC)*; U8 7(NC)* 12(NC)* 13(NC)*

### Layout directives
rule Undefined: (no net found under the mark)

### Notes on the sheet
- Place U1 Close to Q1 and Q2, and minimize distance between Q1_Gate and U1-OUTA, Q2-Gate and U1-OUTB , VSS1 &VSS2 and Q1-Source
- High Voltage
- Place U3 Close to Q5 and Q6, and minimize distance between Q5_Gate and U3-OUTA, Q6-Gate and U3-OUTB , VSS1 &VSS2 and Q5-Source
- Place U2 Close to Q3 and Q4, and minimize distance between Q3_Gate and U2-OUTA, Q4-Gate and U2-OUTB , VSS1 &VSS2 and Q3-Source

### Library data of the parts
C8 C9 C11 C14 C15 C17 C18 C20 C23 = C0805C104K3RACTU: as C3 on sheet MCU011A_PowerStage
C10 C16 C19 = GRM21BR71H105KA12L: CAP, CERM, 1 µF, 50 V, +/- 10%, X7R, 0805; Manufacturer: MuRata; Polarized: N; CompType: Capacitor; Value: 1uF; U/M: EA; Cap_F: 0.000001; Tolerance_%: 10; Value1: Unknown; VDC_V: 50; Value2: 50V; TaMin_C: -55; TaMax_C: 125; Cap_Case: 0805; AEC Category: Q200
C12 C13 C21 C22 C24 C25 = C1206C106K3RACTU: as C2 on sheet MCU011A_PowerStage
D7-D12 = MBRM130LT1G: Diode, Schottky, 30 V, 1 A, POWERMITE; Manufacturer: ON Semiconductor; U/M: EA; Vf_V: 0.38; Value: 30V; Value1: 1A; Value2: 0.38V; Io_A: 1; Vr_V: 30; TJmax_C: 125; AEC Category: Q101
R19 R24 R25 R28 R33 R34 R36 R42 R43 = CRCW08050000Z0EA: RES, 0, 5%, 0.125 W, 0805; Manufacturer: Vishay-Dale; CompType: Resistor; Value: 0; Value_Code: 0000; Tolerance_%: 5; Power_W: 0.125; Value2: 0.125W; VDC_V: 150; TempCo: 200 ppm/C; EIA_Code: E24; U/M: EA; AEC Category: Q200
R20 R26 R29 R35 R38 R44 = CRCW080510R0JNEA: RES, 10, 5%, 0.125 W, 0805; Manufacturer: Vishay-Dale; CompType: Resistor; Value: 10; Value_Code: 10R0; Tolerance_%: 5; Power_W: 0.125; Value2: 0.125W; VDC_V: 150; TempCo: 200 ppm/C; SizeArea_mm2: 2.5; SizeX_mm: 2; SizeY_mm: 1.25; SizeZ_mm: 1.45; EIA_Code: E24; U/M: EA; AEC Category: Q200
R21-R23 R27 R30-R32 R37 R39-R41 R45 = RT0805BRD0710KL: RES, 10.0 k, 0.1%, 0.125 W, 0805; Manufacturer: Yageo America; CompType: Resistor; Value: 10.0k; Res_ohm: 10000; Value_Code: 10k0; Tolerance_%: 0.1; Power_W: 0.125; Value2: 0.125W; VDC_V: 150; TempCo: 25 ppm/C; EIA_Code: E192; U/M: EA; AEC Category: Q200
TP1-TP6 = 5014: Test Point, Multipurpose, Yellow, TH; Manufacturer: Keystone; CompType: Test Point Loop; ContactFinish: Silver
TP_GND1 = 5128: Test Point, Multipurpose, Grey, TH; Manufacturer: Keystone; SymbolCreator: a0412235; CompType: Test Point Loop; ContactFinish: Silver
U5 U7 U8 = UCC21520DWR: 4A/6A, 5.7 kVrms Isolated Dual Channel Gate Driver, DW0016B (SOIC-16); Manufacturer: Texas Instruments; SymbolCreator: a0799628; SizeArea_mm2: 107.12; SizeAreaWB_mm2: 152.52; SizeX_mm: 10.4; SizeY_mm: 10.3; SizeZ_mm: 2.65; CompType: IC; U/M: EA
U6 U9 U10 = RP-1212S: 1 Watt Single Output, TH; Manufacturer: Recom Power; SymbolCreator: a0411947

## Sheet MCU011A_ControllerPower.SchDoc: Board Bias Power Supply
size 431 x 279 mm; Date: Not shown in title block; ApprovedBy: Not shown in title block; CheckedBy: Not shown in title block; Author: Not shown in title block; CompanyName: Not shown in title block; DrawnBy: Manish Bhardwaj; Engineer: Not shown in title block; Organization: Not shown in title block; Address1: Not shown in title block; Address2: Not shown in title block; Address3: Not shown in title block; Address4: Not shown in title block; DocumentNumber: 1; Revision: Use project parameter SCH_Rev; SheetNumber: 9; SheetTotal: 10; PageSetup: Record=PageOptions¦CenterHorizontal=True¦CenterVertical=True¦PrintScale=1.00¦XCorrection=1.00¦YCorrection=1.00¦PrintKind=0¦BorderSize=5000000¦LeftOffset=0¦BottomOffset=0¦Orientation=2¦PaperLength=1000¦PaperWidth=1000¦Scale=100¦PaperSource=15¦PrintQuality=600¦MediaType=1¦DitherType=10¦PaperKind=Letter¦PrintScaleMode=1
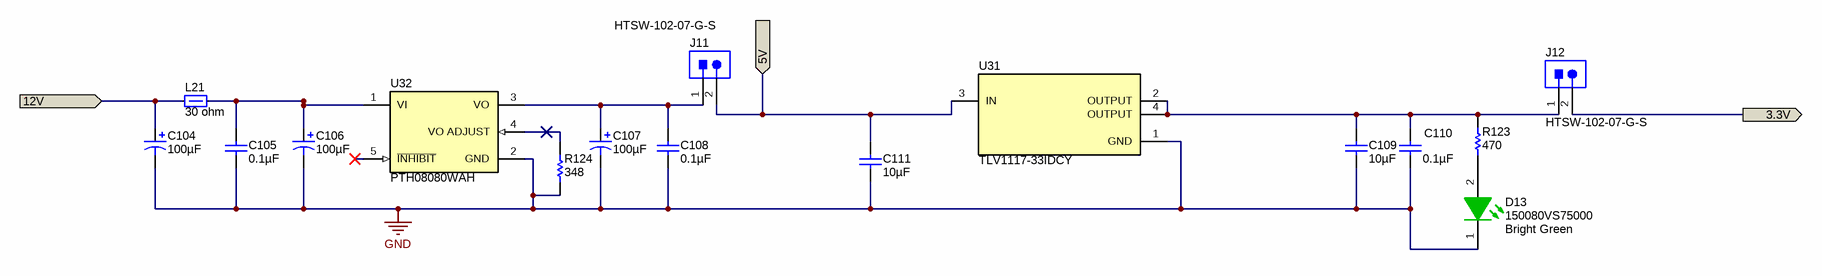
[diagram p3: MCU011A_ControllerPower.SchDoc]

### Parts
C104  ValueDisplayed: 100µF  [SM_RADIAL_6.3BMM]  (hidden comment: EEH-ZA1E101XP)
C105  ValueDisplayed: 0.1µF  [0805]  (hidden comment: C0805C104K3RACTU)
C106  ValueDisplayed: 100µF  [SM_RADIAL_6.3BMM]  (hidden comment: EEH-ZA1E101XP)
C107  ValueDisplayed: 100µF  [SM_RADIAL_6.3BMM]  (hidden comment: EEH-ZA1E101XP)
C108  ValueDisplayed: 0.1µF  [0805]  (hidden comment: C0805C104K3RACTU)
C109  ValueDisplayed: 10µF  [1206_190]  (hidden comment: C1206C106K3RACTU)
C110  ValueDisplayed: 0.1µF  [0805]  (hidden comment: C0805C104K3RACTU)
C111  ValueDisplayed: 10µF  [1206_190]  (hidden comment: C1206C106K3RACTU)
D13  150080VS75000  value Bright Green  [WL-SMCW_Green_0805]
J11  HTSW-102-07-G-S  [Samtec_HTSW-102-07-G-S]
J12  HTSW-102-07-G-S  [Samtec_HTSW-102-07-G-S]
L21  value 30 ohm  [0805_HV]  (hidden comment: MPZ2012S300AT000)
R123  ValueDisplayed: 470  [0805_HV]  (hidden comment: CRCW0805470RFKEA)
R124  ValueDisplayed: 348  [0805_HV]  (hidden comment: CRCW0805348RFKEA)
U31  TLV1117-33IDCY  [DCY0004A_N]
U32  PTH08080WAH  [EUF0005A]

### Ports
3.3V, 5V, 12V (in)

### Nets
3.3V: J12.2 ; port 3.3V
5V: C111.1 J11.2 U31.3(IN) ; port 5V
12V: C104.1(+) L21.2 ; port 12V
GND: C104.2(-) C105.1 C106.2(-) C107.2(-) C108.1 C109.2 C110.1 C111.2 D13.1(K) R124.1 U31.1(GND) U32.2(GND)
NetC105_2: C105.2 C106.1(+) L21.1 U32.1(VI)
NetC107_1: C107.1(+) C108.2 J11.1 U32.3(VO)
NetC109_1: C109.1 C110.2 J12.1 R123.2 U31.2(OUTPUT) U31.4(OUTPUT)
NetD13_2: D13.2(A) R123.1
NetR124_2: R124.2 U32.4(VO_ADJUST)

Not connected (* = marked no-connect by the designer): U32 5(~{INHIBIT})*

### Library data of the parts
C104 C106 C107 = EEHZA1E101XP: CAP, Polymer Hybrid, 100 µF, 25 V, +/- 20%, 30 ohm, 6.3x7.7 SMD; Manufacturer: Panasonic; Polarized: Y; CompType: Capacitor; Value: 100uF; U/M: EA; Cap_F: 0.0001; Tolerance_%: 20; Value1: 30 ohm; VDC_V: 25; Value2: 25V; ESR_ohm: 30; IRMS_A: 2; TaMin_C: -55; TaMax_C: 105; AEC Category: Q200
C105 C108 C110 = C0805C104K3RACTU: CAP, CERM, 0.1 µF, 25 V, +/- 10%, X7R, 0805; Manufacturer: Kemet; Polarized: N; CompType: Capacitor; Value: 0.1uF; U/M: EA; Cap_F: 0.0000001; Tolerance_%: 10; ESR_ohm: 0.064; Value1: 0.064 ohm; VDC_V: 25; Value2: 25V; IRMS_A: 1.64; TaMin_C: -55; TaMax_C: 125; AEC Category: Q200
C109 C111 = C1206C106K3RACTU: as C2 on sheet MCU011A_PowerStage
D13 = 150080VS75000: LED, Bright Green, SMD; Manufacturer: Wurth Elektronik; SymbolCreator: Altium; Type: AlInGaP; Vf_V: 2; Value2: 2V; Io_A: 0.02; Vr_V: 5; Tjmax_C: 85; Power_TotalModule: 0.072; Value1: 0.072W; Angle: 140; U/M: EA
J11 J12 = HTSW-102-07-G-S: Header, 100mil, 2x1, Gold, TH; Manufacturer: Samtec; SymbolCreator: a0412235
L21 = MPZ2012S300AT000: as L1 on sheet MCU011A_PowerStage
R123 = CRCW0805470RFKEA: RES, 470, 1%, 0.125 W, 0805; Manufacturer: Vishay-Dale; CompType: Resistor; Value: 470; Value_Code: 470R; Tolerance_%: 1; Power_W: 0.125; Value2: 0.125W; VDC_V: 150; TempCo: 100 ppm/C; U/M: EA; AEC Category: Q200
R124 = CRCW0805348RFKEA: RES, 348, 1%, 0.125 W, 0805; Manufacturer: Vishay-Dale; CompType: Resistor; Value: 348; Value_Code: 348R; Tolerance_%: 1; Power_W: 0.125; Value2: 0.125W; VDC_V: 150; TempCo: 100 ppm/C; EIA_Code: E96; U/M: EA; AEC Category: Q200
U31 = TLV1117-33IDCY: FIXED LOW-DROPOUT VOLTAGE REGULATOR, DCY0004A; Manufacturer: Texas Instruments; SymbolCreator: a0411947; SizeArea_mm2: 45.5; SizeAreaWB_mm2: 76.5; SizeX_mm: 7; SizeY_mm: 6.5; SizeZ_mm: 1.8; CompType: IC; U/M: EA
U32 = PTH08080WAH: 2.25 A, 4.5 to 18 V Input Wide Adjust Miniature Power Module, -40 to 85 degC, 5-pin Module (EUF5), Pb-Free (RoHS); Manufacturer: Texas Instruments; Alternate PartNumber: Equivalent; Iout(Max)(A): 2.25; Regulated Outputs(#): 1; SubFamily: Non-Isolated POL; Vin(Max)(V): 18; Vin(Min)(V): 4.5; VO Adjustable: TRUE; Vout(Max)(V): 5.5; Vout(Min)(V): 0.9

## Sheet MCU011A_EVM_Hardware.SchDoc: EVM Hardware
size 431 x 279 mm; Date: Not shown in title block; ApprovedBy: Not shown in title block; CheckedBy: Not shown in title block; Author: Not shown in title block; CompanyName: Not shown in title block; DrawnBy: Manish Bhardwaj; Engineer: Not shown in title block; Organization: Not shown in title block; Address1: Not shown in title block; Address2: Not shown in title block; Address3: Not shown in title block; Address4: Not shown in title block; DocumentNumber: 1; Revision: Use project parameter SCH_Rev; SheetNumber: 10; SheetTotal: 10; PageSetup: Record=PageOptions¦CenterHorizontal=True¦CenterVertical=True¦PrintScale=1.00¦XCorrection=1.00¦YCorrection=1.00¦PrintKind=0¦BorderSize=5000000¦LeftOffset=0¦BottomOffset=0¦Orientation=2¦PaperLength=1000¦PaperWidth=1000¦Scale=100¦PaperSource=15¦PrintQuality=600¦MediaType=1¦DitherType=10¦PaperKind=Letter¦PrintScaleMode=1
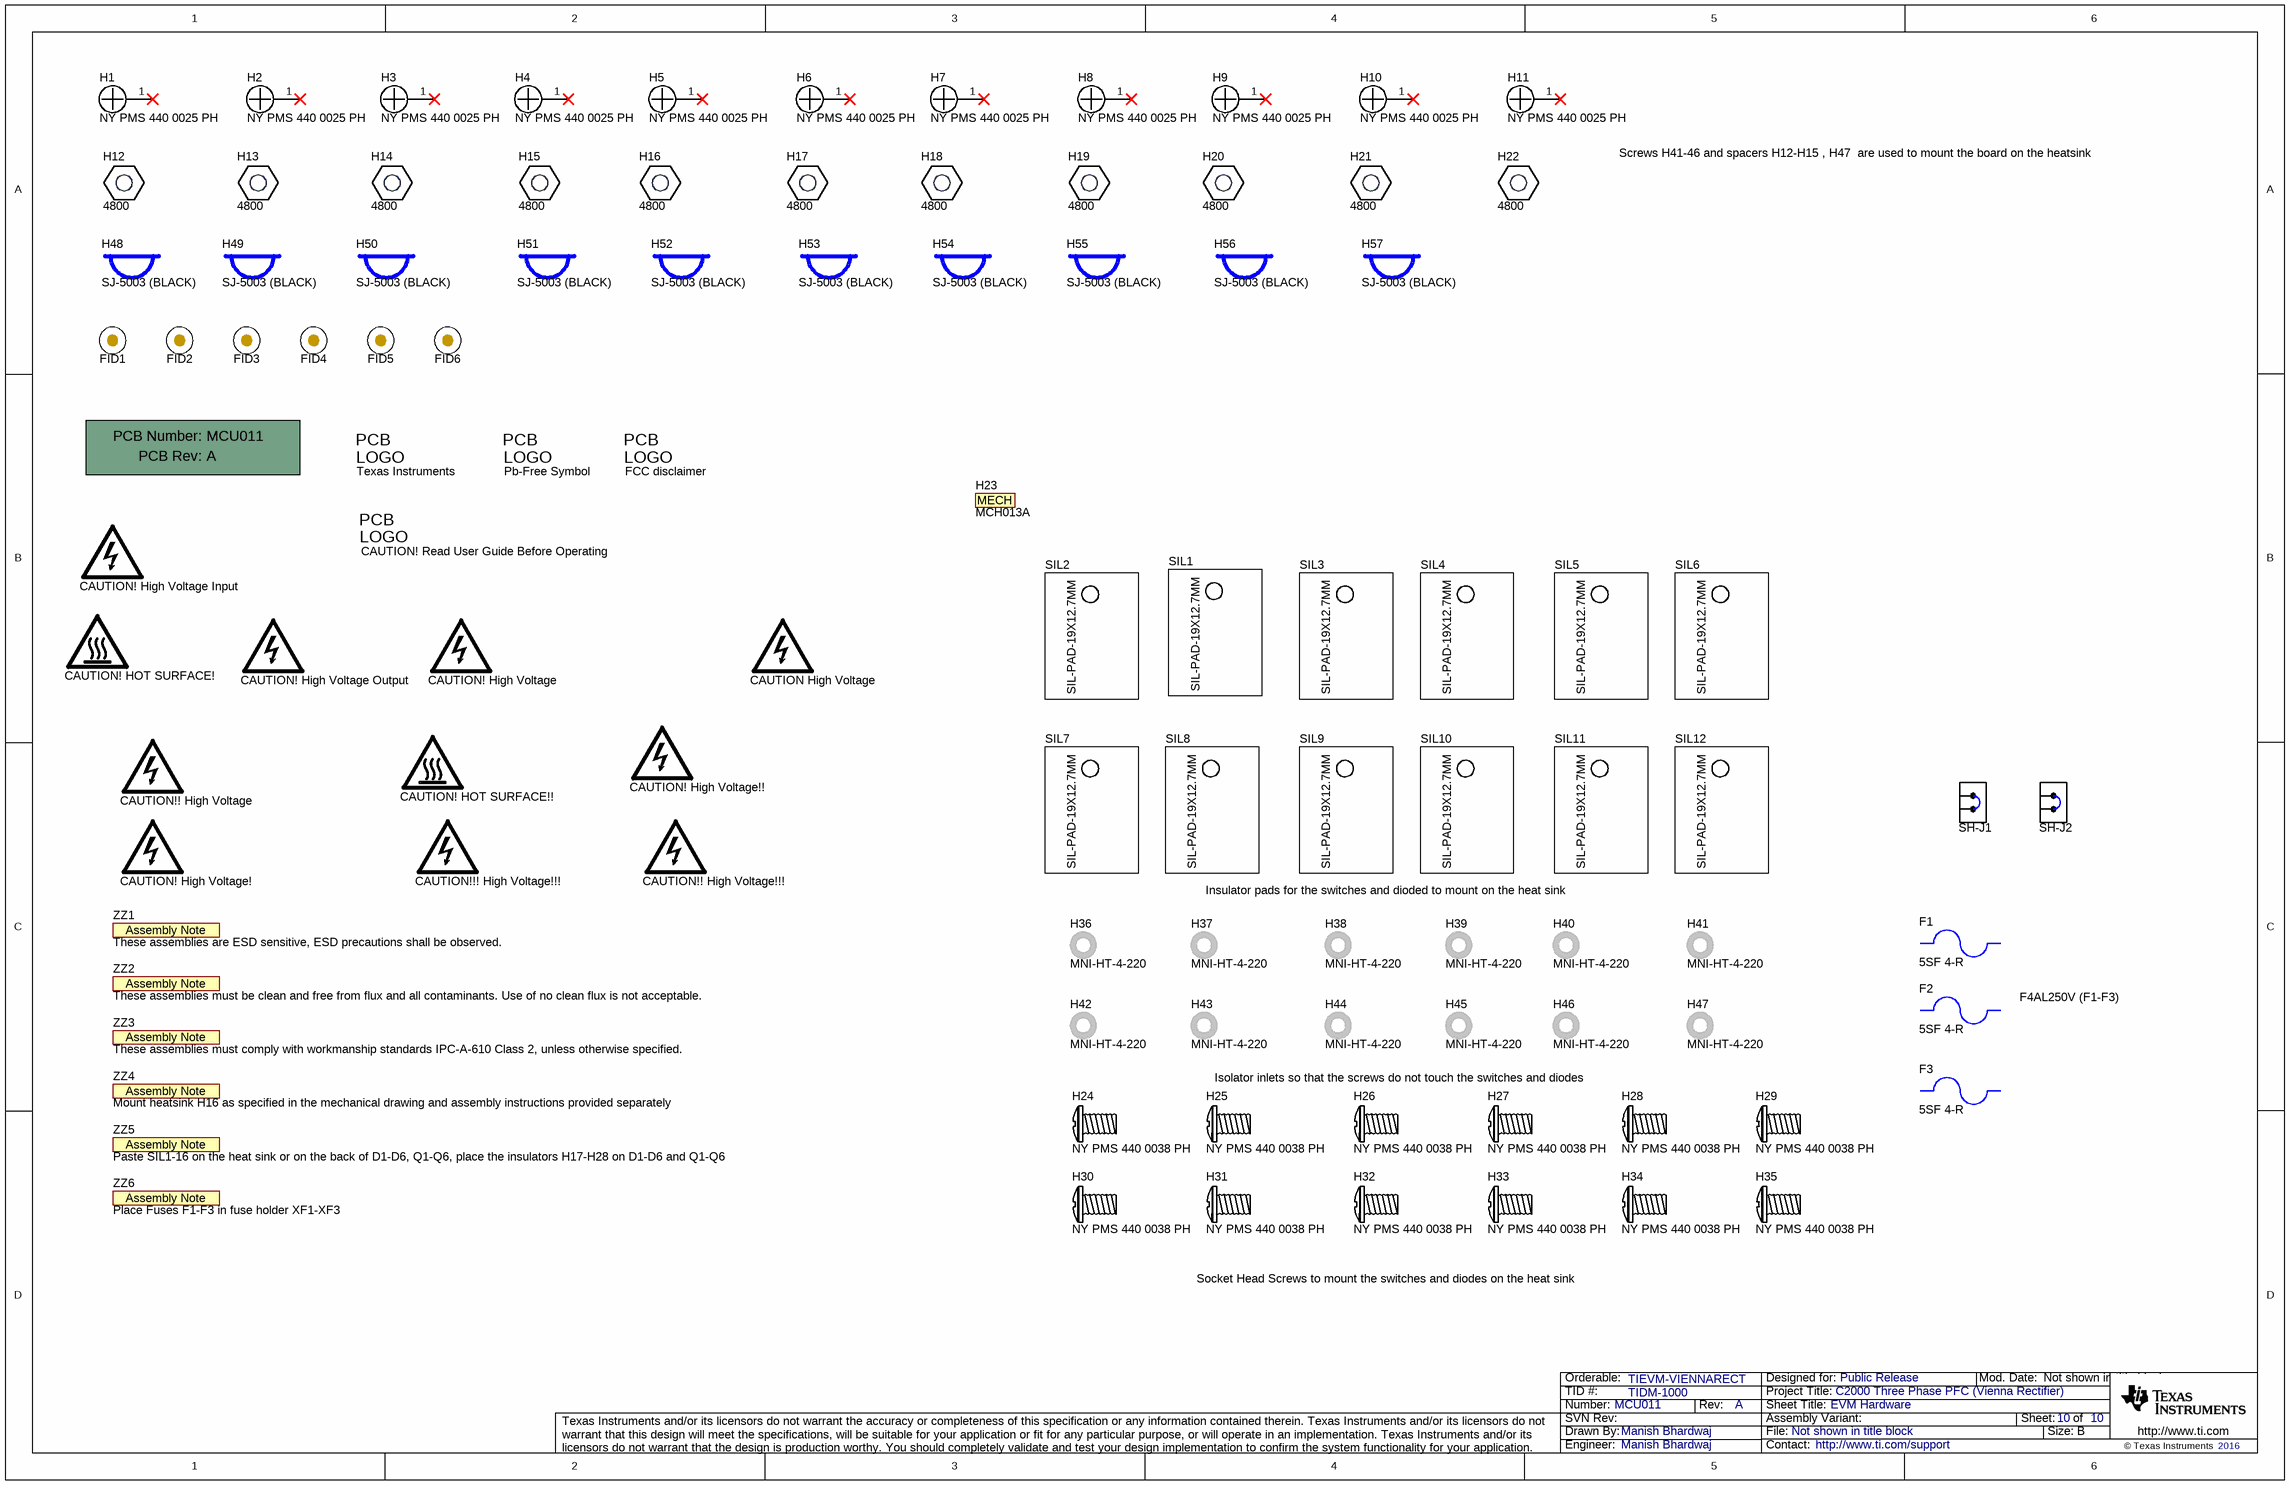
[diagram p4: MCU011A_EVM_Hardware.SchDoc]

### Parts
CAUTION!!!_High_Voltage!!!  DANGER HIGH VOLTAGE  [IEC_HighVoltage_Small]  (value not drawn)  (no BOM)
CAUTION!!_High_Voltage  DANGER HIGH VOLTAGE  [IEC_HighVoltage_Small]  (value not drawn)  (no BOM)
CAUTION!!_High_Voltage!!!  DANGER HIGH VOLTAGE  [IEC_HighVoltage_Small]  (value not drawn)  (no BOM)
CAUTION!_High_Voltage  DANGER HIGH VOLTAGE  [IEC_HighVoltage_Small]  (value not drawn)  (no BOM)
CAUTION!_High_Voltage!  DANGER HIGH VOLTAGE  [IEC_HighVoltage_Small]  (value not drawn)  (no BOM)
CAUTION!_High_Voltage!!  DANGER HIGH VOLTAGE  [IEC_HighVoltage_Small]  (value not drawn)  (no BOM)
CAUTION!_High_Voltage_Input  DANGER HIGH VOLTAGE  [IEC_HighVoltage_Small]  (value not drawn)  (no BOM)
CAUTION!_High_Voltage_Output  DANGER HIGH VOLTAGE  [IEC_HighVoltage_Small]  (value not drawn)  (no BOM)
CAUTION!_HOT_SURFACE!  CAUTION HOT SURFACE  [IEC_HotSurface_Small]  (value not drawn)  (no BOM)
CAUTION!_HOT_SURFACE!!  CAUTION HOT SURFACE  [IEC_HotSurface_Small]  (value not drawn)  (no BOM)
CAUTION!_Read_User_Guide_Before_Operating  CAUTION.  READ USER GUIDE BEFORE USE  [IEC_Caution_Small]  (value not drawn)  (no BOM)
CAUTION_High_Voltage  DANGER HIGH VOLTAGE  [IEC_HighVoltage_Small]  (value not drawn)  (no BOM)
F1  5SF 4-R  (mechanical)
F2  5SF 4-R  (mechanical)
F3  5SF 4-R  (mechanical)
FID1  Fiducial  [Fiducial10-20]  (value not drawn)  (no BOM)
FID2  Fiducial  [Fiducial10-20]  (value not drawn)
FID3  Fiducial  [Fiducial10-20]  (value not drawn)
FID4  Fiducial  [Fiducial10-20]  (value not drawn)  (no BOM)
FID5  Fiducial  [Fiducial10-20]  (value not drawn)
FID6  Fiducial  [Fiducial10-20]  (value not drawn)
H1  NY PMS 440 0025 PH  [NY PMS 440 0025 PH]
H2  NY PMS 440 0025 PH  [NY PMS 440 0025 PH]
H3  NY PMS 440 0025 PH  [NY PMS 440 0025 PH]
H4  NY PMS 440 0025 PH  [NY PMS 440 0025 PH]
H5  NY PMS 440 0025 PH  [NY PMS 440 0025 PH]
H6  NY PMS 440 0025 PH  [NY PMS 440 0025 PH]
H7  NY PMS 440 0025 PH  [NY PMS 440 0025 PH]
H8  NY PMS 440 0025 PH  [NY PMS 440 0025 PH]
H9  NY PMS 440 0025 PH  [NY PMS 440 0025 PH]
H10  NY PMS 440 0025 PH  [NY PMS 440 0025 PH]
H11  NY PMS 440 0025 PH  [NY PMS 440 0025 PH]
H12  4800  [Keystone_4800]  (mechanical)
H13  4800  [Keystone_4800]  (mechanical)
H14  4800  [Keystone_4800]  (mechanical)
H15  4800  [Keystone_4800]  (mechanical)
H16  4800  [Keystone_4800]  (mechanical)
H17  4800  [Keystone_4800]  (mechanical)
H18  4800  [Keystone_4800]  (mechanical)
H19  4800  [Keystone_4800]  (mechanical)
H20  4800  [Keystone_4800]  (mechanical)
H21  4800  [Keystone_4800]  (mechanical)
H22  4800  [Keystone_4800]  (mechanical)
H23  MCH013A  (mechanical)
H24  NY PMS 440 0038 PH  (mechanical)
H25  NY PMS 440 0038 PH  (mechanical)
H26  NY PMS 440 0038 PH  (mechanical)
H27  NY PMS 440 0038 PH  (mechanical)
H28  NY PMS 440 0038 PH  (mechanical)
H29  NY PMS 440 0038 PH  (mechanical)
H30  NY PMS 440 0038 PH  (mechanical)
H31  NY PMS 440 0038 PH  (mechanical)
H32  NY PMS 440 0038 PH  (mechanical)
H33  NY PMS 440 0038 PH  (mechanical)
H34  NY PMS 440 0038 PH  (mechanical)
H35  NY PMS 440 0038 PH  (mechanical)
H36  MNI-HT-4-220  (mechanical)
H37  MNI-HT-4-220  (mechanical)
H38  MNI-HT-4-220  (mechanical)
H39  MNI-HT-4-220  (mechanical)
H40  MNI-HT-4-220  (mechanical)
H41  MNI-HT-4-220  (mechanical)
H42  MNI-HT-4-220  (mechanical)
H43  MNI-HT-4-220  (mechanical)
H44  MNI-HT-4-220  (mechanical)
H45  MNI-HT-4-220  (mechanical)
H46  MNI-HT-4-220  (mechanical)
H47  MNI-HT-4-220  (mechanical)
H48  SJ-5003 (BLACK)  [Bumpon_SJ5003Black]  (mechanical)
H49  SJ-5003 (BLACK)  [Bumpon_SJ5003Black]  (mechanical)
H50  SJ-5003 (BLACK)  [Bumpon_SJ5003Black]  (mechanical)
H51  SJ-5003 (BLACK)  [Bumpon_SJ5003Black]  (mechanical)
H52  SJ-5003 (BLACK)  [Bumpon_SJ5003Black]  (mechanical)
H53  SJ-5003 (BLACK)  [Bumpon_SJ5003Black]  (mechanical)
H54  SJ-5003 (BLACK)  [Bumpon_SJ5003Black]  (mechanical)
H55  SJ-5003 (BLACK)  [Bumpon_SJ5003Black]  (mechanical)
H56  SJ-5003 (BLACK)  [Bumpon_SJ5003Black]  (mechanical)
H57  SJ-5003 (BLACK)  [Bumpon_SJ5003Black]  (mechanical)
Logo1  Texas Instruments  [TI_Stacked_Overlay_Small]  (no BOM)
Logo2  Pb-Free Symbol  [Pb-Free_Overlay_Medium]  (no BOM)
Logo3  FCC disclaimer  [FCC_disclaimer]  (no BOM)
MCU011  Printed Circuit Board of the Design  (value not drawn)  (mechanical)
SH-J1  2SN-BK-G  [2SN-BK-G]  (value not drawn)
SH-J2  2SN-BK-G  [2SN-BK-G]  (value not drawn)
SIL1  SP900S-0.009-AC-58  [SIL-PAD_19x12.7mm]  (value not drawn)  (mechanical)
SIL2  SP900S-0.009-AC-58  [SIL-PAD_19x12.7mm]  (value not drawn)  (mechanical)
SIL3  SP900S-0.009-AC-58  [SIL-PAD_19x12.7mm]  (value not drawn)  (mechanical)
SIL4  SP900S-0.009-AC-58  [SIL-PAD_19x12.7mm]  (value not drawn)  (mechanical)
SIL5  SP900S-0.009-AC-58  [SIL-PAD_19x12.7mm]  (value not drawn)  (mechanical)
SIL6  SP900S-0.009-AC-58  [SIL-PAD_19x12.7mm]  (value not drawn)  (mechanical)
SIL7  SP900S-0.009-AC-58  [SIL-PAD_19x12.7mm]  (value not drawn)  (mechanical)
SIL8  SP900S-0.009-AC-58  [SIL-PAD_19x12.7mm]  (value not drawn)  (mechanical)
SIL9  SP900S-0.009-AC-58  [SIL-PAD_19x12.7mm]  (value not drawn)  (mechanical)
SIL10  SP900S-0.009-AC-58  [SIL-PAD_19x12.7mm]  (value not drawn)  (mechanical)
SIL11  SP900S-0.009-AC-58  [SIL-PAD_19x12.7mm]  (value not drawn)  (mechanical)
SIL12  SP900S-0.009-AC-58  [SIL-PAD_19x12.7mm]  (value not drawn)  (mechanical)
ZZ1  These assemblies are ESD sensitive, ESD precautions shall be observed.  [AssemblyNote]  (no BOM)
ZZ2  These assemblies must be clean and free from flux and all contaminants. Use of no clean flux is not acceptable.  [AssemblyNote]  (no BOM)
ZZ3  These assemblies must comply with workmanship standards IPC-A-610 Class 2, unless otherwise specified.  [AssemblyNote]  (no BOM)
ZZ4  Mount heatsink H16 as specified in the mechanical drawing and assembly instructions provided separately  [AssemblyNote]  (no BOM)
ZZ5  Paste SIL1-16 on the heat sink or on the back of D1-D6, Q1-Q6, place the insulators H17-H28 on D1-D6 and Q1-Q6  [AssemblyNote]  (no BOM)
ZZ6  Place Fuses F1-F3 in fuse holder XF1-XF3  [AssemblyNote]  (no BOM)

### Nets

Not connected (* = marked no-connect by the designer): H1 1*; H2 1*; H3 1*; H4 1*; H5 1*; H6 1*; H7 1*; H8 1*; H9 1*; H10 1*; H11 1*

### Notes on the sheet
- Screws H41-46 and spacers H12-H15 , H47  are used to mount the board on the heatsink
- Insulator pads for the switches and dioded to mount on the heat sink
- F4AL250V (F1-F3)
- Isolator inlets so that the screws do not touch the switches and diodes
- Socket Head Screws to mount the switches and diodes on the heat sink

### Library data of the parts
CAUTION!!!_High_Voltage!!! CAUTION!!_High_Voltage CAUTION!!_High_Voltage!!! CAUTION!_High_Voltage CAUTION!_High_Voltage! CAUTION!_High_Voltage!! CAUTION!_High_Voltage_Input CAUTION!_High_Voltage_Output CAUTION_High_Voltage = IEC_HighVoltage: IEC 61010-1 High Voltage Warning; SymbolCreator: a0412235
CAUTION!_HOT_SURFACE! CAUTION!_HOT_SURFACE!! = IEC_HotSurface: IEC 61010-1 Hot Surface Warning; SymbolCreator: a0412235
CAUTION!_Read_User_Guide_Before_Operating = IEC_Caution: IEC 61010-1 Caution Warning; SymbolCreator: a0412235
F1-F3 = 5SF 4-R: Fuse, 4 A, 250 VAC, N/A; Manufacturer: Bel Fuse; SymbolCreator: a0412235; VAC_V: 250; Interrupt_AC: 40; Irating_A: 4; Rtyp_Ohm: 0.017; MeltingTyp: 26
FID1-FID6 = Fiducial: Fiducial mark.  There is nothing to buy or mount.; SymbolCreator: codlsc
H1-H11 = NY PMS 440 0025 PH: Machine Screw, Round, #4-40 x 1/4, Nylon, Philips panhead; Manufacturer: B&F Fastener Supply; CompType: Hardware; SymbolCreator: codlsc; U/M: EA
H12-H22 = 4800: Standoff, M/F, 0.25", 4-40, Nylon; Manufacturer: Keystone; SymbolCreator: a0412235
H23 = MechPart: 1/4 inches Aluminum sheet cut and tapped for installation of the FETs and Diodes on the board and mounting screws on H1-H11; Manufacturer: Any; SymbolCreator: codlsc; CompType: Mechanical; U/M: EA
H24-H35 = NY PMS 440 0038 PH: Screw, Pan Head , 4-40, 3/8", Nylon; Manufacturer: B&F Fastener Supply; SymbolCreator: a0412235; CompType: Hardware
H36-H47 = MNI-HT-4-220: WASHER SHOULDER #4 POLY SULFIDE; Manufacturer: Essentra Components; SymbolCreator: a0412235
H48-H57 = SJ-5003 (BLACK): Bumpon, Hemisphere, 0.44 X 0.20, Black; Manufacturer: 3M; SymbolCreator: a0412235
Logo1 = TI_Logo: Texas Instrument Corporate Signature; SymbolCreator: codlsc
Logo2 = Pb-Free: SymbolCreator: a0412235
Logo3 = FCC_disclaimer: SymbolCreator: codlsc
MCU011 = PCB: Printed Circuit Board; Manufacturer: Any; PartNumber: MCU011; SymbolCreator: a0412235
SH-J1 SH-J2 = 2SN-BK-G: Shunt, 2mm, Gold plated, Black; Manufacturer: Samtec; Value: 1x2; Note: You can "mate" this to a header by matching the designator.  i.e. use SH-J3 for header J3
SIL1-SIL12 = SP900S-0.009-AC-58: Silcon Thermal Pad; Manufacturer: Bergquist Company; SymbolCreator: a0411947
ZZ1-ZZ6 = AssemblyNote: SymbolCreator: codlsc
